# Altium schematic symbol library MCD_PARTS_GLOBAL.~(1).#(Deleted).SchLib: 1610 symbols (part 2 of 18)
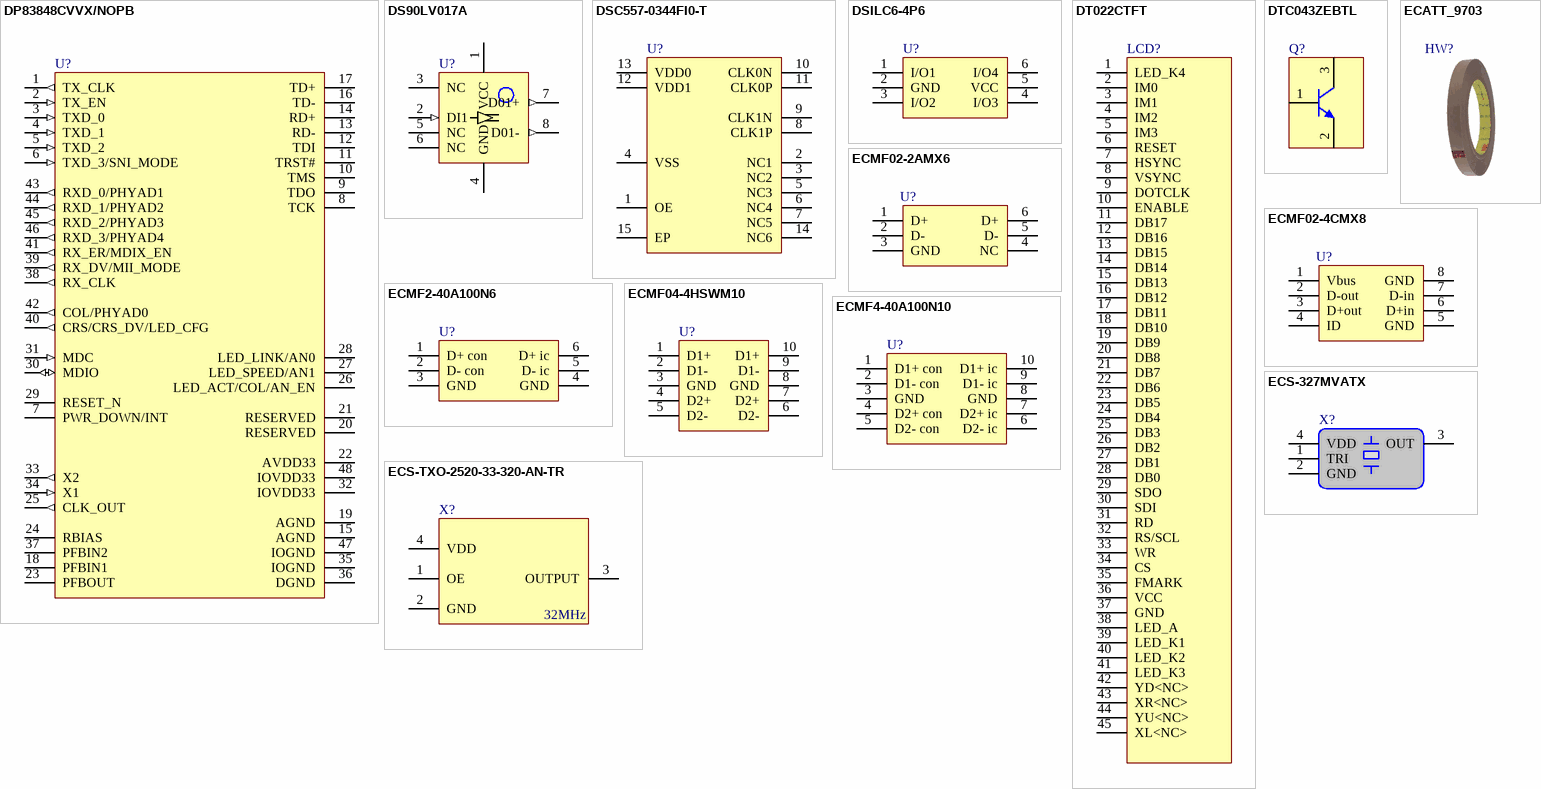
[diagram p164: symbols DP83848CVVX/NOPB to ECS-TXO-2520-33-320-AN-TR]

## DP83848CVVX/NOPB
designator U?
pins: 1 TX_CLK (out), 2 TX_EN (in), 3 TXD_0 (in), 4 TXD_1 (in), 5 TXD_2 (in), 6 TXD_3/SNI_MODE (in), 7 PWR_DOWN/INT, 8 TCK, 9 TDO, 10 TMS, 11 TRST#, 12 TDI, 13 RD-, 14 RD+, 15 AGND, 16 TD-, 17 TD+, 18 PFBIN1, 19 AGND, 20 RESERVED, 21 RESERVED, 22 AVDD33, 23 PFBOUT, 24 RBIAS, 25 CLK_OUT (out), 26 LED_ACT/COL/AN_EN, 27 LED_SPEED/AN1, 28 LED_LINK/AN0, 29 RESET_N, 30 MDIO (io), 31 MDC (in), 32 IOVDD33, 33 X2 (out), 34 X1 (in), 35 IOGND, 36 DGND, 37 PFBIN2, 38 RX_CLK (out), 39 RX_DV/MII_MODE (out), 40 CRS/CRS_DV/LED_CFG (out), 41 RX_ER/MDIX_EN (out), 42 COL/PHYAD0 (out), 43 RXD_0/PHYAD1 (out), 44 RXD_1/PHYAD2 (out), 45 RXD_2/PHYAD3 (out), 46 RXD_3/PHYAD4 (out), 47 IOGND, 48 IOVDD33

## DS90LV017A
designator U?
pins: 1 VCC (power), 2 DI1 (in), 3 NC, 4 GND, 5 NC, 6 NC, 7 D01+ (out), 8 D01- (out)

## DSC557-0344FI0-T
designator U?
pins: 1 OE, 2 NC1, 3 NC2, 4 VSS, 5 NC3, 6 NC4, 7 NC5, 8 CLK1P, 9 CLK1N, 10 CLK0N, 11 CLK0P, 12 VDD1, 13 VDD0, 14 NC6, 15 EP

## DSILC6-4P6
designator U?
pins: 1 I/O1, 2 GND, 3 I/O2, 4 I/O3, 5 VCC, 6 I/O4

## DT022CTFT
designator LCD?
pins: 1 LED_K4 , 2 IM0, 3 IM1, 4 IM2, 5 IM3, 6 RESET, 7 HSYNC, 8 VSYNC, 9 DOTCLK, 10 ENABLE, 11 DB17, 12 DB16, 13 DB15, 14 DB14, 15 DB13, 16 DB12, 17 DB11, 18 DB10, 19 DB9, 20 DB8, 21 DB7, 22 DB6, 23 DB5, 24 DB4, 25 DB3, 26 DB2, 27 DB1, 28 DB0, 29 SDO, 30 SDI, 31 RD, 32 RS/SCL, 33 WR, 34 CS, 35 FMARK, 36 VCC, 37 GND, 38 LED_A, 39 LED_K1, 40 LED_K2, 41 LED_K3, 42 YD<NC>, 43 XR<NC>, 44 YU<NC>, 45 XL<NC>

## DTC043ZEBTL
designator Q?
pins: 1 B, 2 E, 3 C

## ECATT_9703
designator HW?  (mechanical)

## ECMF02-2AMX6
designator U?
pins: 1 D+, 2 D-, 3 GND, 4 NC, 5 D-, 6 D+

## ECMF02-4CMX8
designator U?
pins: 1 Vbus, 2 D-out, 3 D+out, 4 ID, 5 GND, 6 D+in, 7 D-in, 8 GND

## ECMF2-40A100N6
designator U?
pins: 1 D+ con, 2 D- con, 3 GND, 4 GND, 5 D- ic, 6 D+ ic

## ECMF04-4HSWM10
designator U?
pins: 1 D1+, 2 D1-, 3 GND (power), 4 D2+ (oc), 5 D2- (oc), 6 D2-, 7 D2+, 8 GND (power), 9 D1-, 10 D1+

## ECMF4-40A100N10
designator U?
pins: 1 D1+ con, 2 D1- con, 3 GND, 4 D2+ con, 5 D2- con, 6 D2- ic, 7 D2+ ic, 8 GND, 9 D1- ic, 10 D1+ ic

## ECS-327MVATX
designator X?
pins: 1 TRI, 2 GND, 3 OUT, 4 VDD

## ECS-TXO-2520-33-320-AN-TR
designator X?
pins: 1 OE, 2 GND, 3 OUTPUT, 4 VDD

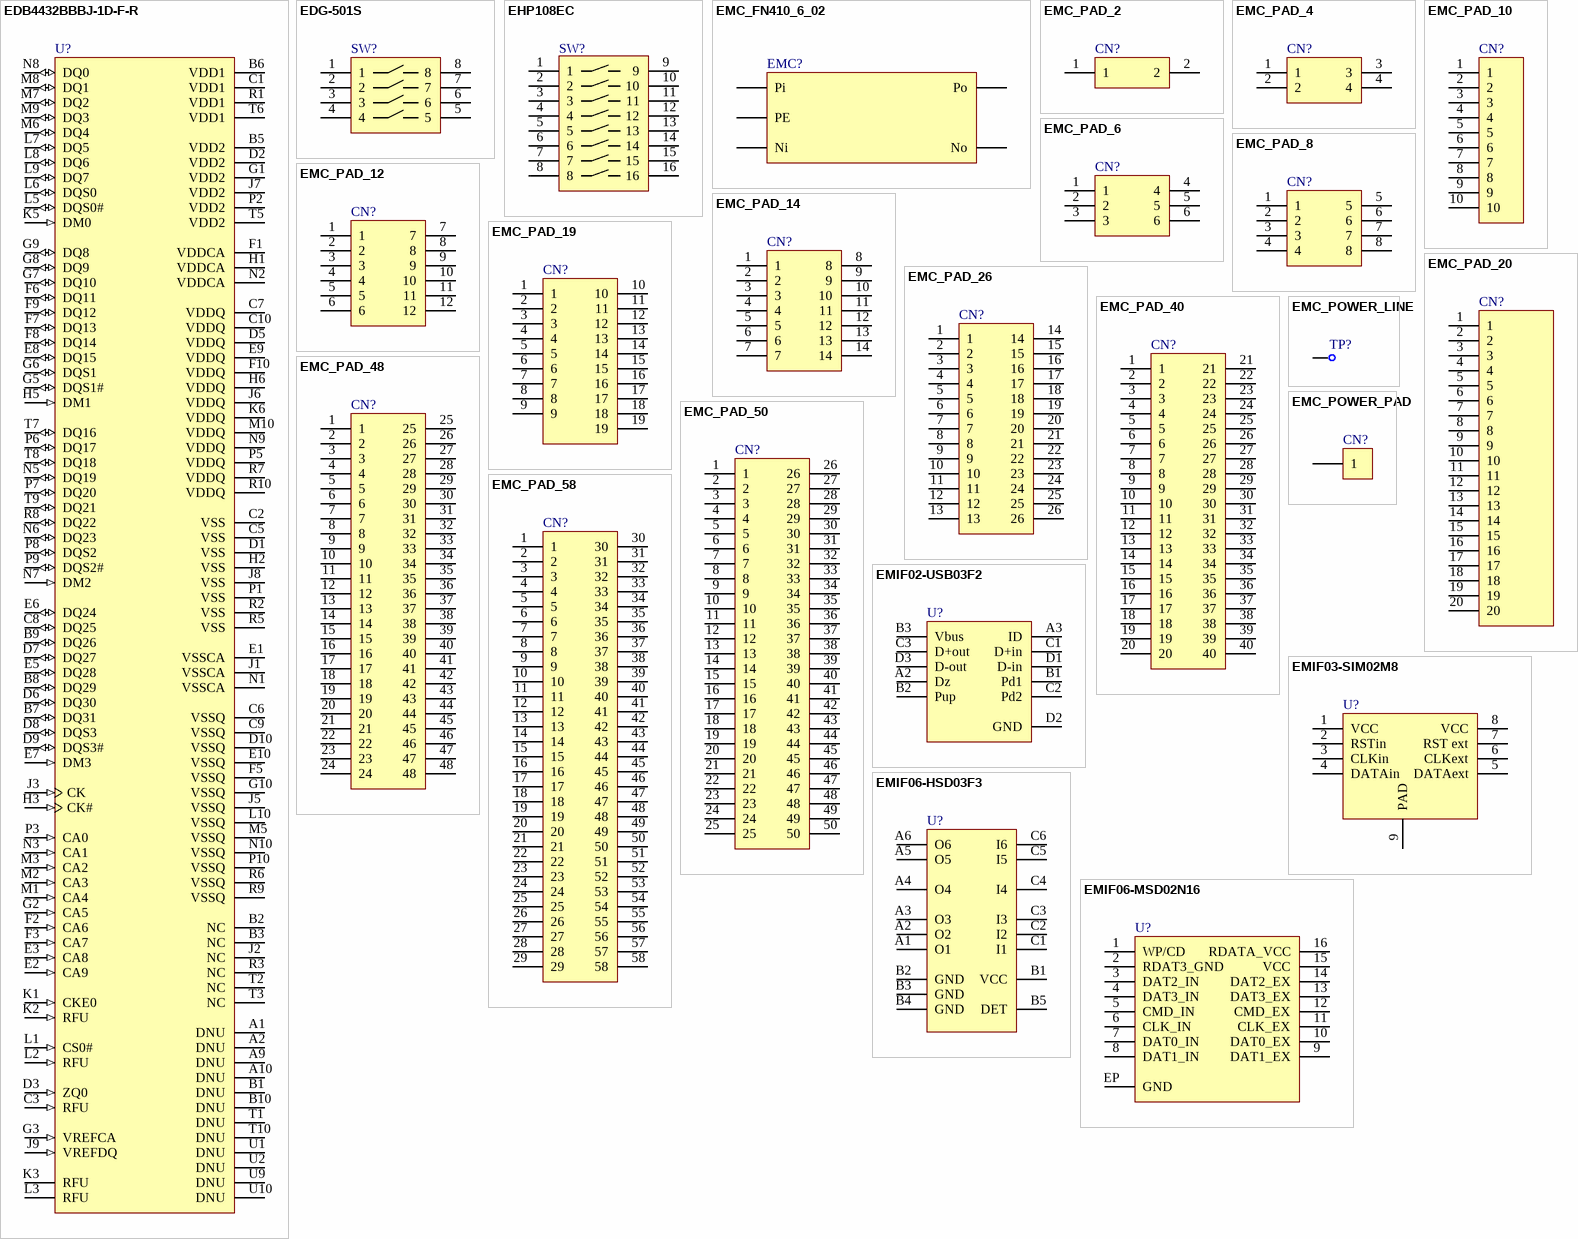
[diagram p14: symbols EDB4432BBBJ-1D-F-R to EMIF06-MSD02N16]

## EDB4432BBBJ-1D-F-R
designator U?
pins: A1 DNU "Do not use: Must be grounded or left floating.", A2 DNU "Do not use: Must be grounded or left floating.", A9 DNU "Do not use: Must be grounded or left floating.", A10 DNU "Do not use: Must be grounded or left floating.", B1 DNU "Do not use: Must be grounded or left floating.", B2 NC "No connect: Not internally connected.", B3 NC "No connect: Not internally connected.", B5 VDD2 (power) "Core power: Supply 2.", B6 VDD1 (power) "Core power: Supply 1.", B7 DQ31 (io) "Data input/output: Bidirectional data bus.", B8 DQ29 (io) "Data input/output: Bidirectional data bus.", B9 DQ26 (io) "Data input/output: Bidirectional data bus.", B10 DNU "Do not use: Must be grounded or left floating.", C1 VDD1 (power) "Core power: Supply 1.", C2 VSS (power) "Common ground.", C3 RFU (in) "External impedance (240 ohm): This signal is used to calibrate the device output impedance.", C5 VSS (power) "Common ground.", C6 VSSQ (power) "DQ ground: Isolated on the die for improved noise immunity.", C7 VDDQ (power) "DQ power supply: Isolated on the die for improved noise immunity.", C8 DQ25 (io) "Data input/output: Bidirectional data bus.", C9 VSSQ (power) "DQ ground: Isolated on the die for improved noise immunity.", C10 VDDQ (power) "DQ power supply: Isolated on the die for improved noise immunity.", D1 VSS (power) "Common ground", D2 VDD2 (power) "Core power: Supply 2.", D3 ZQ0 (in) "External impedance (240 ohm): This signal is used to calibrate the device output impedance.", D5 VDDQ (power) "DQ power supply: Isolated on the die for improved noise immunity.", D6 DQ30 (io) "Data input/output: Bidirectional data bus.", D7 DQ27 (io) "Data input/output: Bidirectional data bus.", D8 DQS3 (io) "Data strobe: The data strobe is bidirectional (used for read and write data) andcomplementary (DQS and DQS#). It is edge-aligned output with read data andcentered input with write data. DQS[3:0]/DQS[3:0]# is DQS for each of (See Datasheet)", D9 DQS3# (io) "Data strobe: The data strobe is bidirectional (used for read and write data) andcomplementary (DQS and DQS#). It is edge-aligned output with read data andcentered input with write data. DQS[3:0]/DQS[3:0]# is DQS for each of (See Datasheet)", D10 VSSQ (power) "DQ ground: Isolated on the die for improved noise immunity.", E1 VSSCA (power) "Command/address ground: Isolated on the die for improved noise immunity.", E2 CA9 (in) "Command/address inputs: Provide the command and address inputs accordingto the command truth table.", E3 CA8 (in) "Command/address inputs: Provide the command and address inputs accordingto the command truth table.", E5 DQ28 (io) "Data input/output: Bidirectional data bus.", E6 DQ24 (io) "Data input/output: Bidirectional data bus.", E7 DM3 (in) "Input data mask: DM is an input mask signal for write data. Although DM ballsare input-only, the DM loading is designed to match that of DQ and DQS balls.DM[3:0] is DM for each of the four data bytes, respectively.", E8 DQ15 (io) "Data input/output: Bidirectional data bus.", E9 VDDQ (power) "DQ power supply: Isolated on the die for improved noise immunity.", E10 VSSQ (power) "DQ ground: Isolated on the die for improved noise immunity.", F1 VDDCA (power) "Command/address power supply: Command/address power supply.", F2 CA6 (in) "Command/address inputs: Provide the command and address inputs accordingto the command truth table.", F3 CA7 (in) "Command/address inputs: Provide the command and address inputs accordingto the command truth table.", F5 VSSQ (power) "DQ ground: Isolated on the die for improved noise immunity.", F6 DQ11 (io) "Data input/output: Bidirectional data bus.", F7 DQ13 (io) "Data input/output: Bidirectional data bus.", F8 DQ14 (io) "Data input/output: Bidirectional data bus.", F9 DQ12 (io) "Data input/output: Bidirectional data bus.", F10 VDDQ (power) "DQ power supply: Isolated on the die for improved noise immunity.", G1 VDD2 (power) "Core power: Supply 2.", G2 CA5 (in) "Command/address inputs: Provide the command and address inputs accordingto the command truth table.", G3 VREFCA (in) "Reference voltage: VREFCA is reference for command/address input buffers,VREFDQ is reference for DQ input buffers.", G5 DQS1# (io) "Data strobe: The data strobe is bidirectional (used for read and write data) andcomplementary (DQS and DQS#). It is edge-aligned output with read data andcentered input with write data. DQS[3:0]/DQS[3:0]# is DQS for each of (See Datasheet)", G6 DQS1 (io) "Data strobe: The data strobe is bidirectional (used for read and write data) andcomplementary (DQS and DQS#). It is edge-aligned output with read data andcentered input with write data. DQS[3:0]/DQS[3:0]# is DQS for each of (See Datasheet)", G7 DQ10 (io) "Data input/output: Bidirectional data bus.", G8 DQ9 (io) "Data input/output: Bidirectional data bus.", G9 DQ8 (io) "Data input/output: Bidirectional data bus.", G10 VSSQ (power) "DQ ground: Isolated on the die for improved noise immunity.", H1 VDDCA (power) "Command/address power supply: Command/address power supply.", H2 VSS (power) "Common ground", H3 CK# (in) "Clock: CK and CK# are differential clock inputs. All CA inputs are sampled onboth rising and falling edges of CK. CS and CKE inputs are sampled at the risingedge of CK. AC timings are referenced to clock.", H5 DM1 (in) "Input data mask: DM is an input mask signal for write data. Although DM ballsare input-only, the DM loading is designed to match that of DQ and DQS balls.DM[3:0] is DM for each of the four data bytes, respectively.", H6 VDDQ (power) "DQ power supply: Isolated on the die for improved noise immunity.", J1 VSSCA (power) "Command/address ground: Isolated on the die for improved noise immunity.", J2 NC "No connect: Not internally connected.", J3 CK (in) "Clock: CK and CK# are differential clock inputs. All CA inputs are sampled onboth rising and falling edges of CK. CS and CKE inputs are sampled at the risingedge of CK. AC timings are referenced to clock.", J5 VSSQ (power) "DQ ground: Isolated on the die for improved noise immunity.", J6 VDDQ (power) "DQ power supply: Isolated on the die for improved noise immunity.", J7 VDD2 (power) "Core power: Supply 2.", J8 VSS (power) "Common ground", J9 VREFDQ (in) "Reference voltage: VREFCA is reference for command/address input buffers,VREFDQ is reference for DQ input buffers.", K1 CKE0 (in) "Clock enable: CKE HIGH activates and CKE LOW deactivates the internal clocksignals, input buffers, and output drivers. Power-saving modes are entered andexited via CKE transitions. CKE is considered part of the command code. (See Datasheet)", K2 RFU (in) "Clock enable: CKE HIGH activates and CKE LOW deactivates the internal clocksignals, input buffers, and output drivers. Power-saving modes are entered andexited via CKE transitions. CKE is considered part of the command code. (See Datasheet)", K3 RFU, K5 DM0 (in) "Input data mask: DM is an input mask signal for write data. Although DM ballsare input-only, the DM loading is designed to match that of DQ and DQS balls.DM[3:0] is DM for each of the four data bytes, respectively.", K6 VDDQ (power) "DQ power supply: Isolated on the die for improved noise immunity.", L1 CS0# (in) "Chip select: CS# is considered part of the command code and is sampled at therising edge of CK.", L2 RFU (in) "Chip select: CS# is considered part of the command code and is sampled at therising edge of CK.", L3 RFU, L5 DQS0# (io) "Data strobe: The data strobe is bidirectional (used for read and write data) andcomplementary (DQS and DQS#). It is edge-aligned output with read data andcentered input with write data. DQS[3:0]/DQS[3:0]# is DQS for each of (See Datasheet)", L6 DQS0 (io) "Data strobe: The data strobe is bidirectional (used for read and write data) andcomplementary (DQS and DQS#). It is edge-aligned output with read data andcentered input with write data. DQS[3:0]/DQS[3:0]# is DQS for each of (See Datasheet)", L7 DQ5 (io) "Data input/output: Bidirectional data bus.", L8 DQ6 (io) "Data input/output: Bidirectional data bus.", L9 DQ7 (io) "Data input/output: Bidirectional data bus.", L10 VSSQ (power) "DQ ground: Isolated on the die for improved noise immunity.", M1 CA4 (in) "Command/address inputs: Provide the command and address inputs accordingto the command truth table.", M2 CA3 (in) "Command/address inputs: Provide the command and address inputs accordingto the command truth table.", M3 CA2 (in) "Command/address inputs: Provide the command and address inputs accordingto the command truth table.", M5 VSSQ (power) "DQ ground: Isolated on the die for improved noise immunity.", M6 DQ4 (io) "Data input/output: Bidirectional data bus.", M7 DQ2 (io) "Data input/output: Bidirectional data bus.", M8 DQ1 (io) "Data input/output: Bidirectional data bus.", M9 DQ3 (io) "Data input/output: Bidirectional data bus.", M10 VDDQ (power) "DQ power supply: Isolated on the die for improved noise immunity.", N1 VSSCA (power) "Command/address ground: Isolated on the die for improved noise immunity.", N2 VDDCA (power) "Command/address power supply: Command/address power supply.", N3 CA1 (in) "Command/address inputs: Provide the command and address inputs accordingto the command truth table.", N5 DQ19 (io) "Data input/output: Bidirectional data bus.", N6 DQ23 (io) "Data input/output: Bidirectional data bus.", N7 DM2 (in) "Input data mask: DM is an input mask signal for write data. Although DM ballsare input-only, the DM loading is designed to match that of DQ and DQS balls.DM[3:0] is DM for each of the four data bytes, respectively.", N8 DQ0 (io) "Data input/output: Bidirectional data bus.", N9 VDDQ (power) "DQ power supply: Isolated on the die for improved noise immunity.", N10 VSSQ (power) "DQ ground: Isolated on the die for improved noise immunity.", P1 VSS (power) "Common ground", P2 VDD2 (power) "Core power: Supply 2.", P3 CA0 (in) "Command/address inputs: Provide the command and address inputs accordingto the command truth table.", P5 VDDQ (power) "DQ power supply: Isolated on the die for improved noise immunity.", P6 DQ17 (io) "Data input/output: Bidirectional data bus.", P7 DQ20 (io) "Data input/output: Bidirectional data bus.", P8 DQS2 (io) "Data strobe: The data strobe is bidirectional (used for read and write data) andcomplementary (DQS and DQS#). It is edge-aligned output with read data andcentered input with write data. DQS[3:0]/DQS[3:0]# is DQS for each of (See Datasheet)", P9 DQS2# (io) "Data strobe: The data strobe is bidirectional (used for read and write data) andcomplementary (DQS and DQS#). It is edge-aligned output with read data andcentered input with write data. DQS[3:0]/DQS[3:0]# is DQS for each of (See Datasheet)", P10 VSSQ (power) "DQ ground: Isolated on the die for improved noise immunity.", R1 VDD1 (power) "Core power: Supply 1.", R2 VSS (power) "Common ground", R3 NC "No connect: Not internally connected.", R5 VSS (power) "Common ground", R6 VSSQ (power) "DQ ground: Isolated on the die for improved noise immunity.", R7 VDDQ (power) "DQ power supply: Isolated on the die for improved noise immunity.", R8 DQ22 (io) "Data input/output: Bidirectional data bus.", R9 VSSQ (power) "DQ ground: Isolated on the die for improved noise immunity.", R10 VDDQ (power) "DQ power supply: Isolated on the die for improved noise immunity.", T1 DNU "Do not use: Must be grounded or left floating.", T2 NC "No connect: Not internally connected.", T3 NC "No connect: Not internally connected.", T5 VDD2 (power) "Core power: Supply 2.", T6 VDD1 (power) "Core power: Supply 1.", T7 DQ16 (io) "Data input/output: Bidirectional data bus.", T8 DQ18 (io) "Data input/output: Bidirectional data bus.", T9 DQ21 (io) "Data input/output: Bidirectional data bus.", T10 DNU "Do not use: Must be grounded or left floating.", U1 DNU "Do not use: Must be grounded or left floating.", U2 DNU "Do not use: Must be grounded or left floating.", U9 DNU "Do not use: Must be grounded or left floating.", U10 DNU "Do not use: Must be grounded or left floating."

## EDG-501S
designator SW?
pins: 1, 2, 3, 4, 5, 6, 7, 8

## EHP108EC
designator SW?
pins: 1, 2, 3, 4, 5, 6, 7, 8, 9, 10, 11, 12, 13, 14, 15, 16

## EMC_FN410_6_02
designator EMC?
pins: Ni, No, PE, Pi, Po

## EMC_PAD_2
designator CN?  (no BOM)
pins: 1, 2

## EMC_PAD_4
designator CN?  (no BOM)
pins: 1, 2, 3, 4

## EMC_PAD_6
designator CN?  (no BOM)
pins: 1, 2, 3, 4, 5, 6

## EMC_PAD_8
designator CN?  (no BOM)
pins: 1, 2, 3, 4, 5, 6, 7, 8

## EMC_PAD_10
designator CN?  (no BOM)
pins: 1, 2, 3, 4, 5, 6, 7, 8, 9, 10

## EMC_PAD_12
designator CN?  (no BOM)
pins: 1, 2, 3, 4, 5, 6, 7, 8, 9, 10, 11, 12

## EMC_PAD_14
designator CN?  (no BOM)
pins: 1, 2, 3, 4, 5, 6, 7, 8, 9, 10, 11, 12, 13, 14

## EMC_PAD_19
designator CN?  (no BOM)
pins: 1, 2, 3, 4, 5, 6, 7, 8, 9, 10, 11, 12, 13, 14, 15, 16, 17, 18, 19

## EMC_PAD_20
designator CN?  (no BOM)
pins: 1, 2, 3, 4, 5, 6, 7, 8, 9, 10, 11, 12, 13, 14, 15, 16, 17, 18, 19, 20

## EMC_PAD_26
designator CN?  (no BOM)
pins: 1, 2, 3, 4, 5, 6, 7, 8, 9, 10, 11, 12, 13, 14, 15, 16, 17, 18, 19, 20, 21, 22, 23, 24, 25, 26

## EMC_PAD_40
designator CN?  (no BOM)
pins: 1, 2, 3, 4, 5, 6, 7, 8, 9, 10, 11, 12, 13, 14, 15, 16, 17, 18, 19, 20, 21, 22, 23, 24, 25, 26, 27, 28, 29, 30, 31, 32, 33, 34, 35, 36, 37, 38, 39, 40

## EMC_PAD_48
designator CN?  (no BOM)
pins: 1, 2, 3, 4, 5, 6, 7, 8, 9, 10, 11, 12, 13, 14, 15, 16, 17, 18, 19, 20, 21, 22, 23, 24, 25, 26, 27, 28, 29, 30, 31, 32, 33, 34, 35, 36, 37, 38, 39, 40, 41, 42, 43, 44, 45, 46, 47, 48

## EMC_PAD_50
designator CN?  (no BOM)
pins: 1, 2, 3, 4, 5, 6, 7, 8, 9, 10, 11, 12, 13, 14, 15, 16, 17, 18, 19, 20, 21, 22, 23, 24, 25, 26, 27, 28, 29, 30, 31, 32, 33, 34, 35, 36, 37, 38, 39, 40, 41, 42, 43, 44, 45, 46, 47, 48, 49, 50

## EMC_PAD_58
designator CN?  (no BOM)
pins: 1, 2, 3, 4, 5, 6, 7, 8, 9, 10, 11, 12, 13, 14, 15, 16, 17, 18, 19, 20, 21, 22, 23, 24, 25, 26, 27, 28, 29, 30, 31, 32, 33, 34, 35, 36, 37, 38, 39, 40, 41, 42, 43, 44, 45, 46, 47, 48, 49, 50, 51, 52, 53, 54, 55, 56, 57, 58

## EMC_POWER_LINE
designator TP?  (no BOM)
pins: 1

## EMC_POWER_PAD
designator CN?  (no BOM)
pins: 1

## EMIF02-USB03F2
designator U?
pins: A2 Dz, A3 ID, B1 Pd1, B2 Pup, B3 Vbus, C1 D+in, C2 Pd2, C3 D+out, D1 D-in, D2 GND, D3 D-out

## EMIF03-SIM02M8
designator U?
pins: 1 VCC, 2 RSTin, 3 CLKin, 4 DATAin, 5 DATAext, 6 CLKext, 7 RST ext, 8 VCC, 9 PAD

## EMIF06-HSD03F3
designator U?
pins: A1 O1, A2 O2, A3 O3, A4 O4, A5 O5, A6 O6, B1 VCC, B2 GND, B3 GND, B4 GND, B5 DET, C1 I1, C2 I2, C3 I3, C4 I4, C5 I5, C6 I6

## EMIF06-MSD02N16
designator U?
pins: 1 WP/CD, 2 RDAT3_GND, 3 DAT2_IN, 4 DAT3_IN, 5 CMD_IN, 6 CLK_IN, 7 DAT0_IN, 8 DAT1_IN, 9 DAT1_EX, 10 DAT0_EX, 11 CLK_EX, 12 CMD_EX, 13 DAT3_EX, 14 DAT2_EX, 15 VCC, 16 RDATA_VCC, EP GND
1 alternate drawing of the same symbol

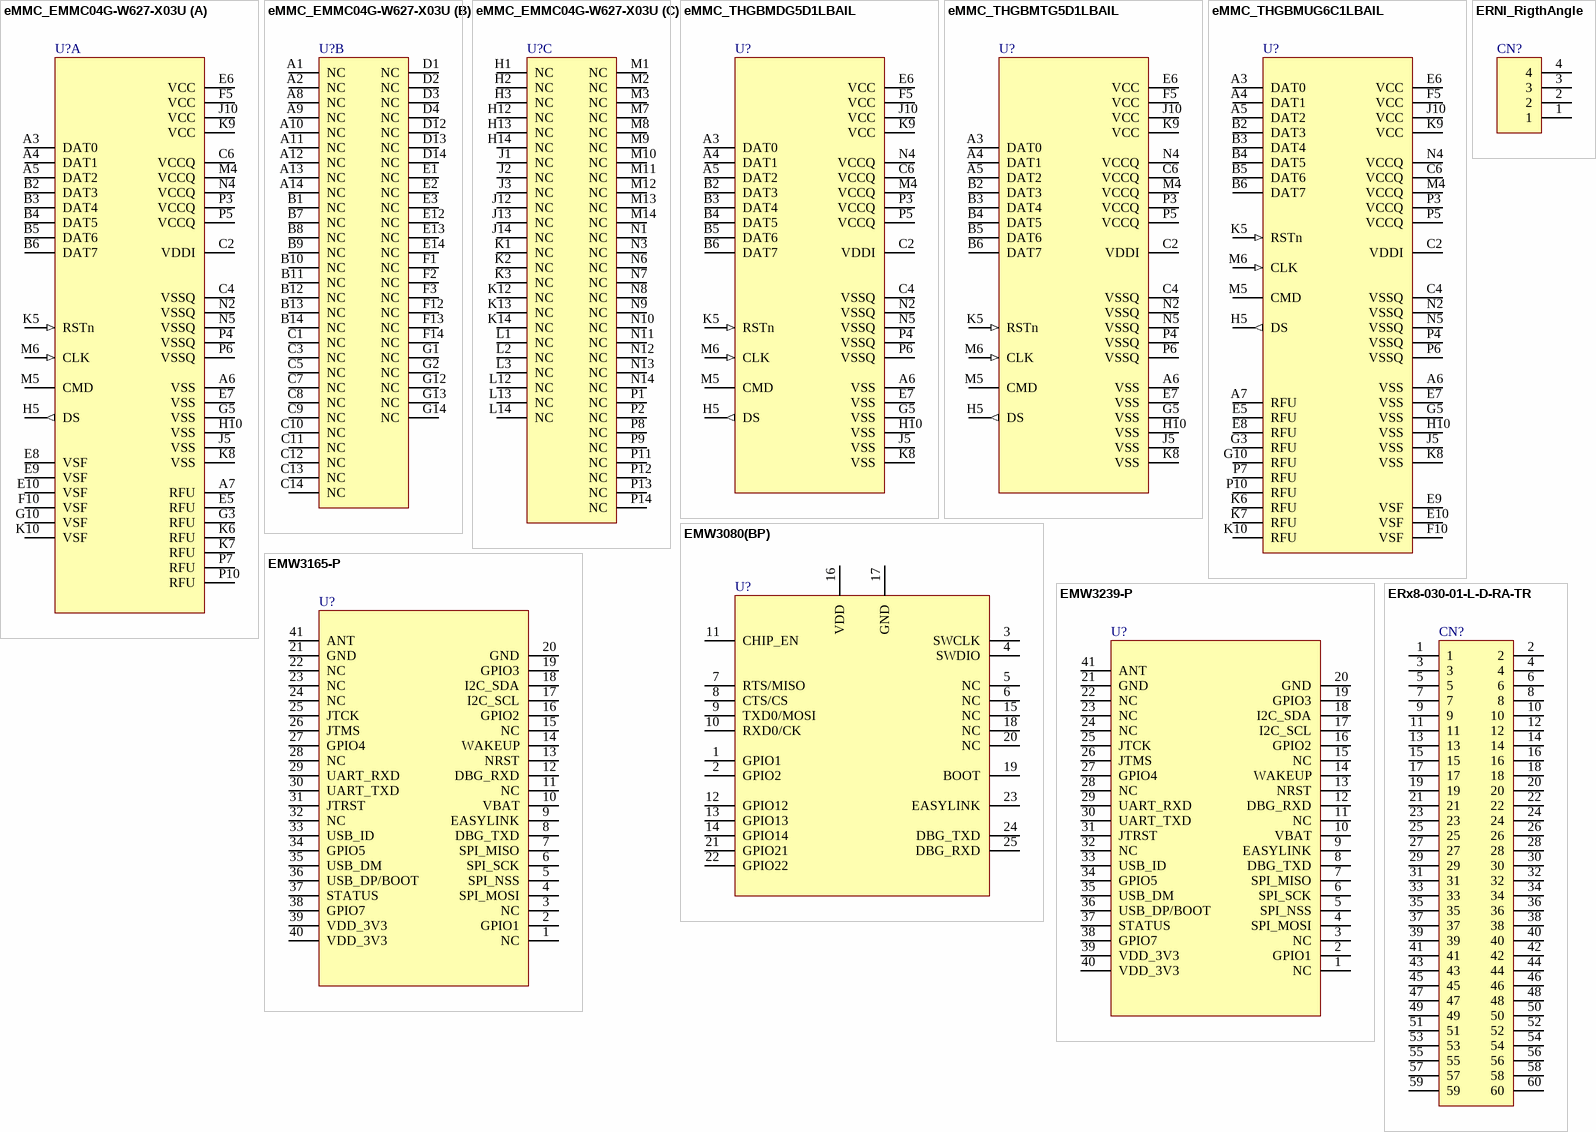
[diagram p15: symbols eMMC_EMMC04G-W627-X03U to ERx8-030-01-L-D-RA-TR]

## eMMC_EMMC04G-W627-X03U
designator U?
part A pins: A3 DAT0, A4 DAT1, A5 DAT2, A6 VSS, A7 RFU, B2 DAT3, B3 DAT4, B4 DAT5, B5 DAT6, B6 DAT7, C2 VDDI, C4 VSSQ, C6 VCCQ, E5 RFU, E6 VCC, E7 VSS, E8 VSF, E9 VSF, E10 VSF, F5 VCC, F10 VSF, G3 RFU, G5 VSS, G10 VSF, H5 DS (out), H10 VSS, J5 VSS, J10 VCC, K5 RSTn (in), K6 RFU, K7 RFU, K8 VSS, K9 VCC, K10 VSF, M4 VCCQ, M5 CMD, M6 CLK (in), N2 VSSQ, N4 VCCQ, N5 VSSQ, P3 VCCQ, P4 VSSQ, P5 VCCQ, P6 VSSQ, P7 RFU, P10 RFU
part B pins: A1 NC, A2 NC, A8 NC, A9 NC, A10 NC, A11 NC, A12 NC, A13 NC, A14 NC, B1 NC, B7 NC, B8 NC, B9 NC, B10 NC, B11 NC, B12 NC, B13 NC, B14 NC, C1 NC, C3 NC, C5 NC, C7 NC, C8 NC, C9 NC, C10 NC, C11 NC, C12 NC, C13 NC, C14 NC, D1 NC, D2 NC, D3 NC, D4 NC, D12 NC, D13 NC, D14 NC, E1 NC, E2 NC, E3 NC, E12 NC, E13 NC, E14 NC, F1 NC, F2 NC, F3 NC, F12 NC, F13 NC, F14 NC, G1 NC, G2 NC, G12 NC, G13 NC, G14 NC
part C pins: H1 NC, H2 NC, H3 NC, H12 NC, H13 NC, H14 NC, J1 NC, J2 NC, J3 NC, J12 NC, J13 NC, J14 NC, K1 NC, K2 NC, K3 NC, K12 NC, K13 NC, K14 NC, L1 NC, L2 NC, L3 NC, L12 NC, L13 NC, L14 NC, M1 NC, M2 NC, M3 NC, M7 NC, M8 NC, M9 NC, M10 NC, M11 NC, M12 NC, M13 NC, M14 NC, N1 NC, N3 NC, N6 NC, N7 NC, N8 NC, N9 NC, N10 NC, N11 NC, N12 NC, N13 NC, N14 NC, P1 NC, P2 NC, P8 NC, P9 NC, P11 NC, P12 NC, P13 NC, P14 NC

## eMMC_THGBMDG5D1LBAIL
designator U?
pins: A3 DAT0, A4 DAT1, A5 DAT2, A6 VSS, B2 DAT3, B3 DAT4, B4 DAT5, B5 DAT6, B6 DAT7, C2 VDDI, C4 VSSQ, C6 VCCQ, E6 VCC, E7 VSS, F5 VCC, G5 VSS, H5 DS (out), H10 VSS, J5 VSS, J10 VCC, K5 RSTn (in), K8 VSS, K9 VCC, M4 VCCQ, M5 CMD, M6 CLK (in), N2 VSSQ, N4 VCCQ, N5 VSSQ, P3 VCCQ, P4 VSSQ, P5 VCCQ, P6 VSSQ

## eMMC_THGBMTG5D1LBAIL
designator U?
pins: A3 DAT0, A4 DAT1, A5 DAT2, A6 VSS, B2 DAT3, B3 DAT4, B4 DAT5, B5 DAT6, B6 DAT7, C2 VDDI, C4 VSSQ, C6 VCCQ, E6 VCC, E7 VSS, F5 VCC, G5 VSS, H5 DS (out), H10 VSS, J5 VSS, J10 VCC, K5 RSTn (in), K8 VSS, K9 VCC, M4 VCCQ, M5 CMD, M6 CLK (in), N2 VSSQ, N4 VCCQ, N5 VSSQ, P3 VCCQ, P4 VSSQ, P5 VCCQ, P6 VSSQ

## eMMC_THGBMUG6C1LBAIL
designator U?
pins: A3 DAT0, A4 DAT1, A5 DAT2, A6 VSS, A7 RFU, B2 DAT3, B3 DAT4, B4 DAT5, B5 DAT6, B6 DAT7, C2 VDDI, C4 VSSQ, C6 VCCQ, E5 RFU, E6 VCC, E7 VSS, E8 RFU, E9 VSF, E10 VSF, F5 VCC, F10 VSF, G3 RFU, G5 VSS, G10 RFU, H5 DS (out), H10 VSS, J5 VSS, J10 VCC, K5 RSTn (in), K6 RFU, K7 RFU, K8 VSS, K9 VCC, K10 RFU, M4 VCCQ, M5 CMD, M6 CLK (in), N2 VSSQ, N4 VCCQ, N5 VSSQ, P3 VCCQ, P4 VSSQ, P5 VCCQ, P6 VSSQ, P7 RFU, P10 RFU

## EMW3080(BP)
designator U?
pins: 1 GPIO1, 2 GPIO2, 3 SWCLK, 4 SWDIO, 5 NC, 6 NC, 7 RTS/MISO, 8 CTS/CS, 9 TXD0/MOSI, 10 RXD0/CK, 11 CHIP_EN, 12 GPIO12, 13 GPIO13, 14 GPIO14, 15 NC, 16 VDD, 17 GND, 18 NC, 19 BOOT, 20 NC, 21 GPIO21, 22 GPIO22, 23 EASYLINK, 24 DBG_TXD, 25 DBG_RXD

## EMW3165-P
designator U?
pins: 1 NC, 2 GPIO1, 3 NC, 4 SPI_MOSI, 5 SPI_NSS, 6 SPI_SCK, 7 SPI_MISO, 8 DBG_TXD, 9 EASYLINK, 10 VBAT, 11 NC, 12 DBG_RXD, 13 NRST, 14 WAKEUP, 15 NC, 16 GPIO2, 17 I2C_SCL, 18 I2C_SDA, 19 GPIO3, 20 GND, 21 GND, 22 NC, 23 NC, 24 NC, 25 JTCK, 26 JTMS, 27 GPIO4, 28 NC, 29 UART_RXD, 30 UART_TXD, 31 JTRST, 32 NC, 33 USB_ID, 34 GPIO5, 35 USB_DM, 36 USB_DP/BOOT, 37 STATUS, 38 GPIO7, 39 VDD_3V3, 40 VDD_3V3, 41 ANT

## EMW3239-P
designator U?
pins: 1 NC, 2 GPIO1, 3 NC, 4 SPI_MOSI, 5 SPI_NSS, 6 SPI_SCK, 7 SPI_MISO, 8 DBG_TXD, 9 EASYLINK, 10 VBAT, 11 NC, 12 DBG_RXD, 13 NRST, 14 WAKEUP, 15 NC, 16 GPIO2, 17 I2C_SCL, 18 I2C_SDA, 19 GPIO3, 20 GND, 21 GND, 22 NC, 23 NC, 24 NC, 25 JTCK, 26 JTMS, 27 GPIO4, 28 NC, 29 UART_RXD, 30 UART_TXD, 31 JTRST, 32 NC, 33 USB_ID, 34 GPIO5, 35 USB_DM, 36 USB_DP/BOOT, 37 STATUS, 38 GPIO7, 39 VDD_3V3, 40 VDD_3V3, 41 ANT

## ERNI_RigthAngle
designator CN?
pins: 1, 2, 3, 4

## ERx8-030-01-L-D-RA-TR
designator CN?
pins: 1, 2, 3, 4, 5, 6, 7, 8, 9, 10, 11, 12, 13, 14, 15, 16, 17, 18, 19, 20, 21, 22, 23, 24, 25, 26, 27, 28, 29, 30, 31, 32, 33, 34, 35, 36, 37, 38, 39, 40, 41, 42, 43, 44, 45, 46, 47, 48, 49, 50, 51, 52, 53, 54, 55, 56, 57, 58, 59, 60

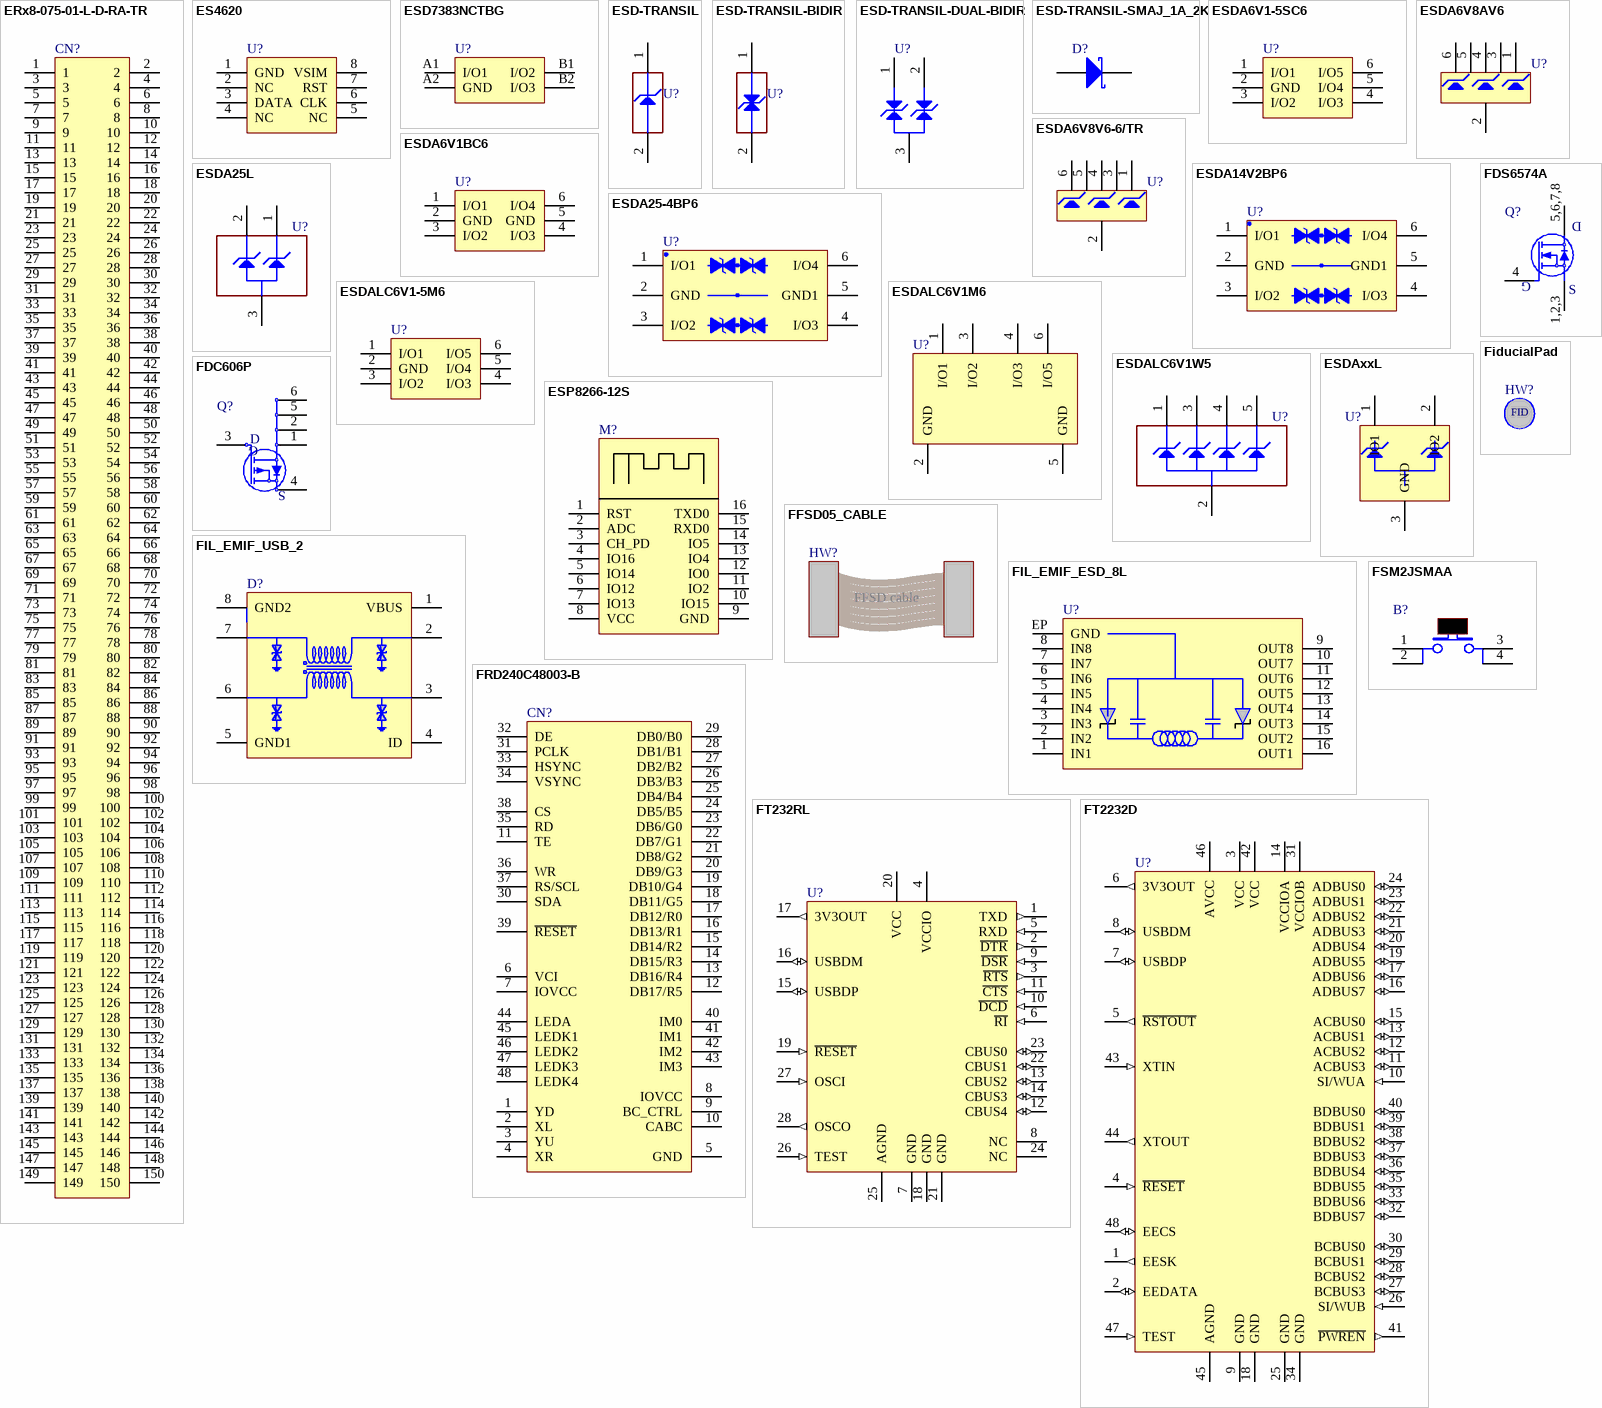
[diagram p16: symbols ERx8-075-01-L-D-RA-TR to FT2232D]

## ERx8-075-01-L-D-RA-TR
designator CN?
pins: 1, 2, 3, 4, 5, 6, 7, 8, 9, 10, 11, 12, 13, 14, 15, 16, 17, 18, 19, 20, 21, 22, 23, 24, 25, 26, 27, 28, 29, 30, 31, 32, 33, 34, 35, 36, 37, 38, 39, 40, 41, 42, 43, 44, 45, 46, 47, 48, 49, 50, 51, 52, 53, 54, 55, 56, 57, 58, 59, 60, 61, 62, 63, 64, 65, 66, 67, 68, 69, 70, 71, 72, 73, 74, 75, 76, 77, 78, 79, 80, 81, 82, 83, 84, 85, 86, 87, 88, 89, 90, 91, 92, 93, 94, 95, 96, 97, 98, 99, 100, 101, 102, 103, 104, 105, 106, 107, 108, 109, 110, 111, 112, 113, 114, 115, 116, 117, 118, 119, 120, 121, 122, 123, 124, 125, 126, 127, 128, 129, 130, 131, 132, 133, 134, 135, 136, 137, 138, 139, 140, 141, 142, 143, 144, 145, 146, 147, 148, 149, 150

## ES4620
designator U?
pins: 1 GND, 2 NC, 3 DATA, 4 NC, 5 NC, 6 CLK, 7 RST, 8 VSIM

## ESD7383NCTBG
designator U?
pins: A1 I/O1, A2 GND, B1 I/O2, B2 I/O3

## ESD-TRANSIL
designator U?
pins: 1 IO1, 2 GND

## ESD-TRANSIL-BIDIR
designator U?
pins: 1 IO1, 2 GND

## ESD-TRANSIL-DUAL-BIDIR
designator U?
pins: 1, 2, 3

## ESD-TRANSIL-SMAJ_1A_2K
designator D?
pins: 1 A, 2 K

## ESDA6V1-5SC6
designator U?
pins: 1 I/O1, 2 GND, 3 I/O2, 4 I/O3, 5 I/O4, 6 I/O5

## ESDA6V1BC6
designator U?
pins: 1 I/O1, 2 GND, 3 I/O2, 4 I/O3, 5 GND, 6 I/O4

## ESDA6V8AV6
designator U?
pins: 1, 2, 3, 4, 5, 6

## ESDA6V8V6-6/TR
designator U?
pins: 1, 2, 3, 4, 5, 6

## ESDA14V2BP6
designator U?
pins: 1 I/O1, 2 GND, 3 I/O2, 4 I/O3, 5 GND1, 6 I/O4

## ESDA25-4BP6
designator U?
pins: 1 I/O1, 2 GND, 3 I/O2, 4 I/O3, 5 GND1, 6 I/O4

## ESDA25L
designator U?
pins: 1 IO1, 2 IO2, 3 GND

## ESDALC6V1-5M6
designator U?
pins: 1 I/O1, 2 GND, 3 I/O2, 4 I/O3, 5 I/O4, 6 I/O5

## ESDALC6V1M6
designator U?
pins: 1 I/O1, 2 GND, 3 I/O2, 4 I/O3, 5 GND, 6 I/O5

## ESDALC6V1W5
designator U?
pins: 1 IO1, 2 GND, 3 IO2, 4 IO3, 5 IO4

## ESDAxxL
designator U?
pins: 1 IO1, 2 IO2, 3 GND

## ESP8266-12S
designator M?
pins: 1 RST, 2 ADC, 3 CH_PD, 4 IO16, 5 IO14, 6 IO12, 7 IO13, 8 VCC, 9 GND, 10 IO15, 11 IO2, 12 IO0, 13 IO4, 14 IO5, 15 RXD0, 16 TXD0

## FDC606P
designator Q?
pins: 1 S, 2 S, 3 G, 4 S, 5 D, 6 D

## FDS6574A
designator Q?
pins: 1,2,3 S, 4 G, 5,6,7,8 D

## FFSD05_CABLE
designator HW?

## FiducialPad
designator HW?  (no BOM)

## FIL_EMIF_ESD_8L
designator U?
pins: 1 IN1, 2 IN2, 3 IN3, 4 IN4, 5 IN5, 6 IN6, 7 IN7, 8 IN8, 9 OUT8, 10 OUT7, 11 OUT6, 12 OUT5, 13 OUT4, 14 OUT3, 15 OUT2, 16 OUT1, EP GND

## FIL_EMIF_USB_2
designator D?
pins: 1 VBUS, 2 D-1, 3 D+1, 4 ID, 5 GND1, 6 D+2, 7 D-2, 8 GND2

## FRD240C48003-B
designator CN?
pins: 1 YD, 2 XL, 3 YU, 4 XR, 5 GND, 6 VCI, 7 IOVCC, 8 IOVCC, 9 BC_CTRL, 10 CABC, 11 TE, 12 DB17/R5, 13 DB16/R4, 14 DB15/R3, 15 DB14/R2, 16 DB13/R1, 17 DB12/R0, 18 DB11/G5, 19 DB10/G4, 20 DB9/G3, 21 DB8/G2, 22 DB7/G1, 23 DB6/G0, 24 DB5/B5, 25 DB4/B4, 26 DB3/B3, 27 DB2/B2, 28 DB1/B1, 29 DB0/B0, 30 SDA, 31 PCLK, 32 DE, 33 HSYNC, 34 VSYNC, 35 RD, 36 WR, 37 RS/SCL, 38 CS, 39 ~{RESET}, 40 IM0, 41 IM1, 42 IM2, 43 IM3, 44 LEDA, 45 LEDK1, 46 LEDK2, 47 LEDK3, 48 LEDK4

## FSM2JSMAA
designator B?
pins: 1, 2, 3, 4

## FT232RL
designator U?
pins: 1 TXD (out), 2 ~{DTR} (out), 3 ~{RTS} (out), 4 VCCIO (power), 5 RXD (in), 6 ~{RI} (in), 7 GND (power), 8 NC, 9 ~{DSR} (in), 10 ~{DCD} (in), 11 ~{CTS} (in), 12 CBUS4 (io), 13 CBUS2 (io), 14 CBUS3 (io), 15 USBDP (io), 16 USBDM (io), 17 3V3OUT (out), 18 GND (power), 19 ~{RESET} (in), 20 VCC (power), 21 GND (power), 22 CBUS1 (io), 23 CBUS0 (io), 24 NC, 25 AGND (power), 26 TEST (in), 27 OSCI (in), 28 OSCO (out)

## FT2232D
designator U?
pins: 1 EESK (out), 2 EEDATA (io), 3 VCC (power), 4 ~{RESET} (in), 5 ~{RSTOUT} (out), 6 3V3OUT (out), 7 USBDP (io), 8 USBDM (io), 9 GND (power), 10 SI/WUA (in), 11 ACBUS3 (io), 12 ACBUS2 (io), 13 ACBUS1 (io), 14 VCCIOA (power), 15 ACBUS0 (io), 16 ADBUS7 (io), 17 ADBUS6 (io), 18 GND (power), 19 ADBUS5 (io), 20 ADBUS4 (io), 21 ADBUS3 (io), 22 ADBUS2 (io), 23 ADBUS1 (io), 24 ADBUS0 (io), 25 GND (power), 26 SI/WUB (in), 27 BCBUS3 (io), 28 BCBUS2 (io), 29 BCBUS1 (io), 30 BCBUS0 (io), 31 VCCIOB (power), 32 BDBUS7 (io), 33 BDBUS6 (io), 34 GND (power), 35 BDBUS5 (io), 36 BDBUS4 (io), 37 BDBUS3 (io), 38 BDBUS2 (io), 39 BDBUS1 (io), 40 BDBUS0 (io), 41 ~{PWREN} (out), 42 VCC (power), 43 XTIN (in), 44 XTOUT (out), 45 AGND (power), 46 AVCC (power), 47 TEST (in), 48 EECS (io)

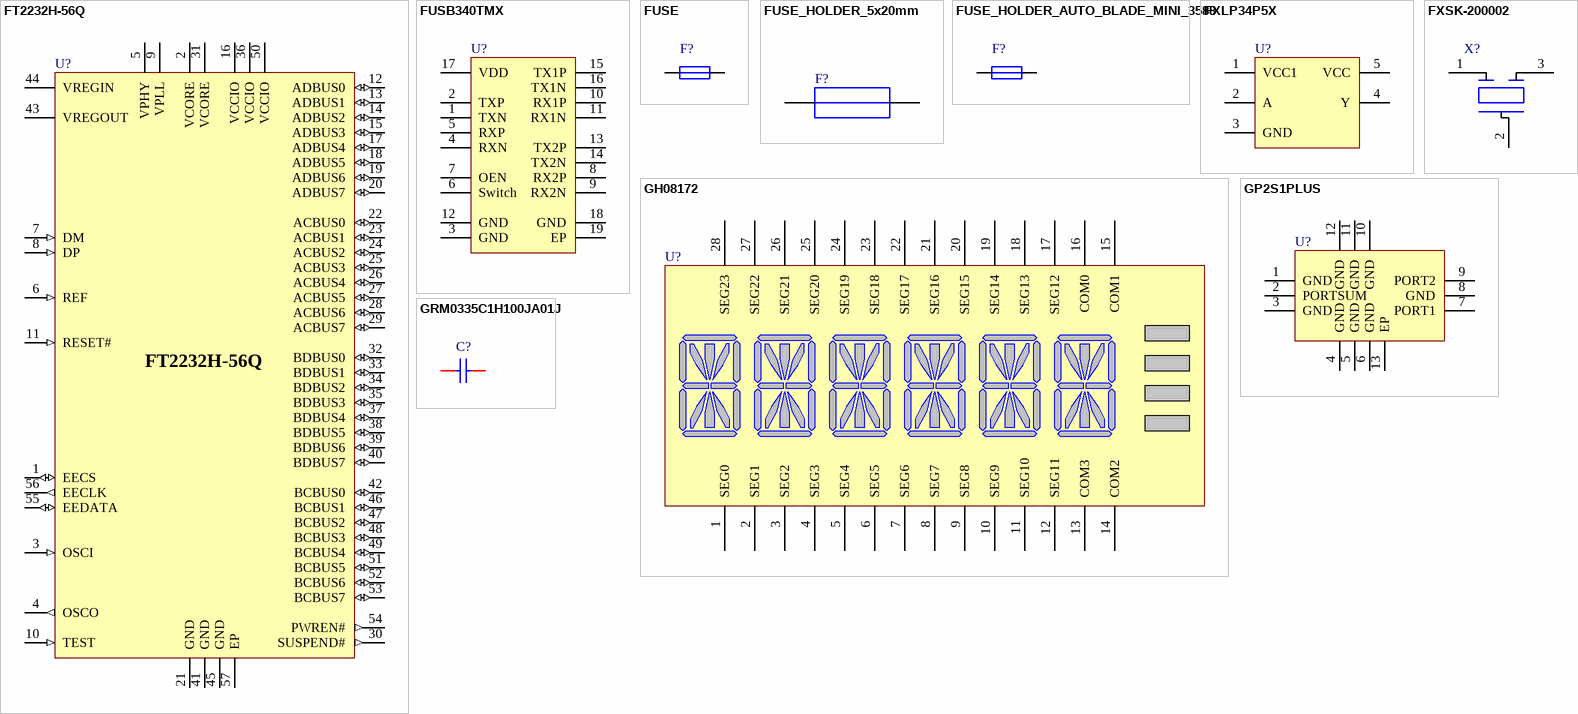
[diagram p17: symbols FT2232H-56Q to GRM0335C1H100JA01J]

## FT2232H-56Q
designator U?
pins: 1 EECS (io), 2 VCORE (power), 3 OSCI (in), 4 OSCO (out), 5 VPHY (power), 6 REF (in), 7 DM (in), 8 DP (in), 9 VPLL (power), 10 TEST (in), 11 RESET# (in), 12 ADBUS0 (io), 13 ADBUS1 (io), 14 ADBUS2 (io), 15 ADBUS3 (io), 16 VCCIO (power), 17 ADBUS4 (io), 18 ADBUS5 (io), 19 ADBUS6 (io), 20 ADBUS7 (io), 21 GND (power), 22 ACBUS0 (io), 23 ACBUS1 (io), 24 ACBUS2 (io), 25 ACBUS3 (io), 26 ACBUS4 (io), 27 ACBUS5 (io), 28 ACBUS6 (io), 29 ACBUS7 (io), 30 SUSPEND# (out), 31 VCORE (power), 32 BDBUS0 (io), 33 BDBUS1 (io), 34 BDBUS2 (io), 35 BDBUS3 (io), 36 VCCIO (power), 37 BDBUS4 (io), 38 BDBUS5 (io), 39 BDBUS6 (io), 40 BDBUS7 (io), 41 GND (power), 42 BCBUS0 (io), 43 VREGOUT (power), 44 VREGIN (power), 45 GND (power), 46 BCBUS1 (io), 47 BCBUS2 (io), 48 BCBUS3 (io), 49 BCBUS4 (io), 50 VCCIO (power), 51 BCBUS5 (io), 52 BCBUS6 (io), 53 BCBUS7 (io), 54 PWREN# (out), 55 EEDATA (io), 56 EECLK (out), 57 EP (power)

## FUSB340TMX
designator U?
pins: 1 TXN, 2 TXP, 3 GND, 4 RXN, 5 RXP, 6 Switch, 7 OEN, 8 RX2P, 9 RX2N, 10 RX1P, 11 RX1N, 12 GND, 13 TX2P, 14 TX2N, 15 TX1P, 16 TX1N, 17 VDD, 18 GND, 19 EP

## FUSE
designator F?
pins: 1, 2

## FUSE_HOLDER_5x20mm
designator F?
pins: 1, 2

## FUSE_HOLDER_AUTO_BLADE_MINI_3588
designator F?
pins: 1, 2

## FXLP34P5X
designator U?
pins: 1 VCC1, 2 A, 3 GND, 4 Y, 5 VCC

## FXSK-200002
designator X?
pins: 1 "Xin", 2, 3 "XOUT"

## GH08172
designator U?
pins: 1 SEG0, 2 SEG1, 3 SEG2, 4 SEG3, 5 SEG4, 6 SEG5, 7 SEG6, 8 SEG7, 9 SEG8, 10 SEG9, 11 SEG10, 12 SEG11, 13 COM3, 14 COM2, 15 COM1, 16 COM0, 17 SEG12, 18 SEG13, 19 SEG14, 20 SEG15, 21 SEG16, 22 SEG17, 23 SEG18, 24 SEG19, 25 SEG20, 26 SEG21, 27 SEG22, 28 SEG23

## GP2S1PLUS
designator U?
pins: 1 GND, 2 PORTSUM, 3 GND, 4 GND, 5 GND, 6 GND, 7 PORT1, 8 GND, 9 PORT2, 10 GND, 11 GND, 12 GND, 13 EP

## GRM0335C1H100JA01J
designator C?
pins: 1, 2

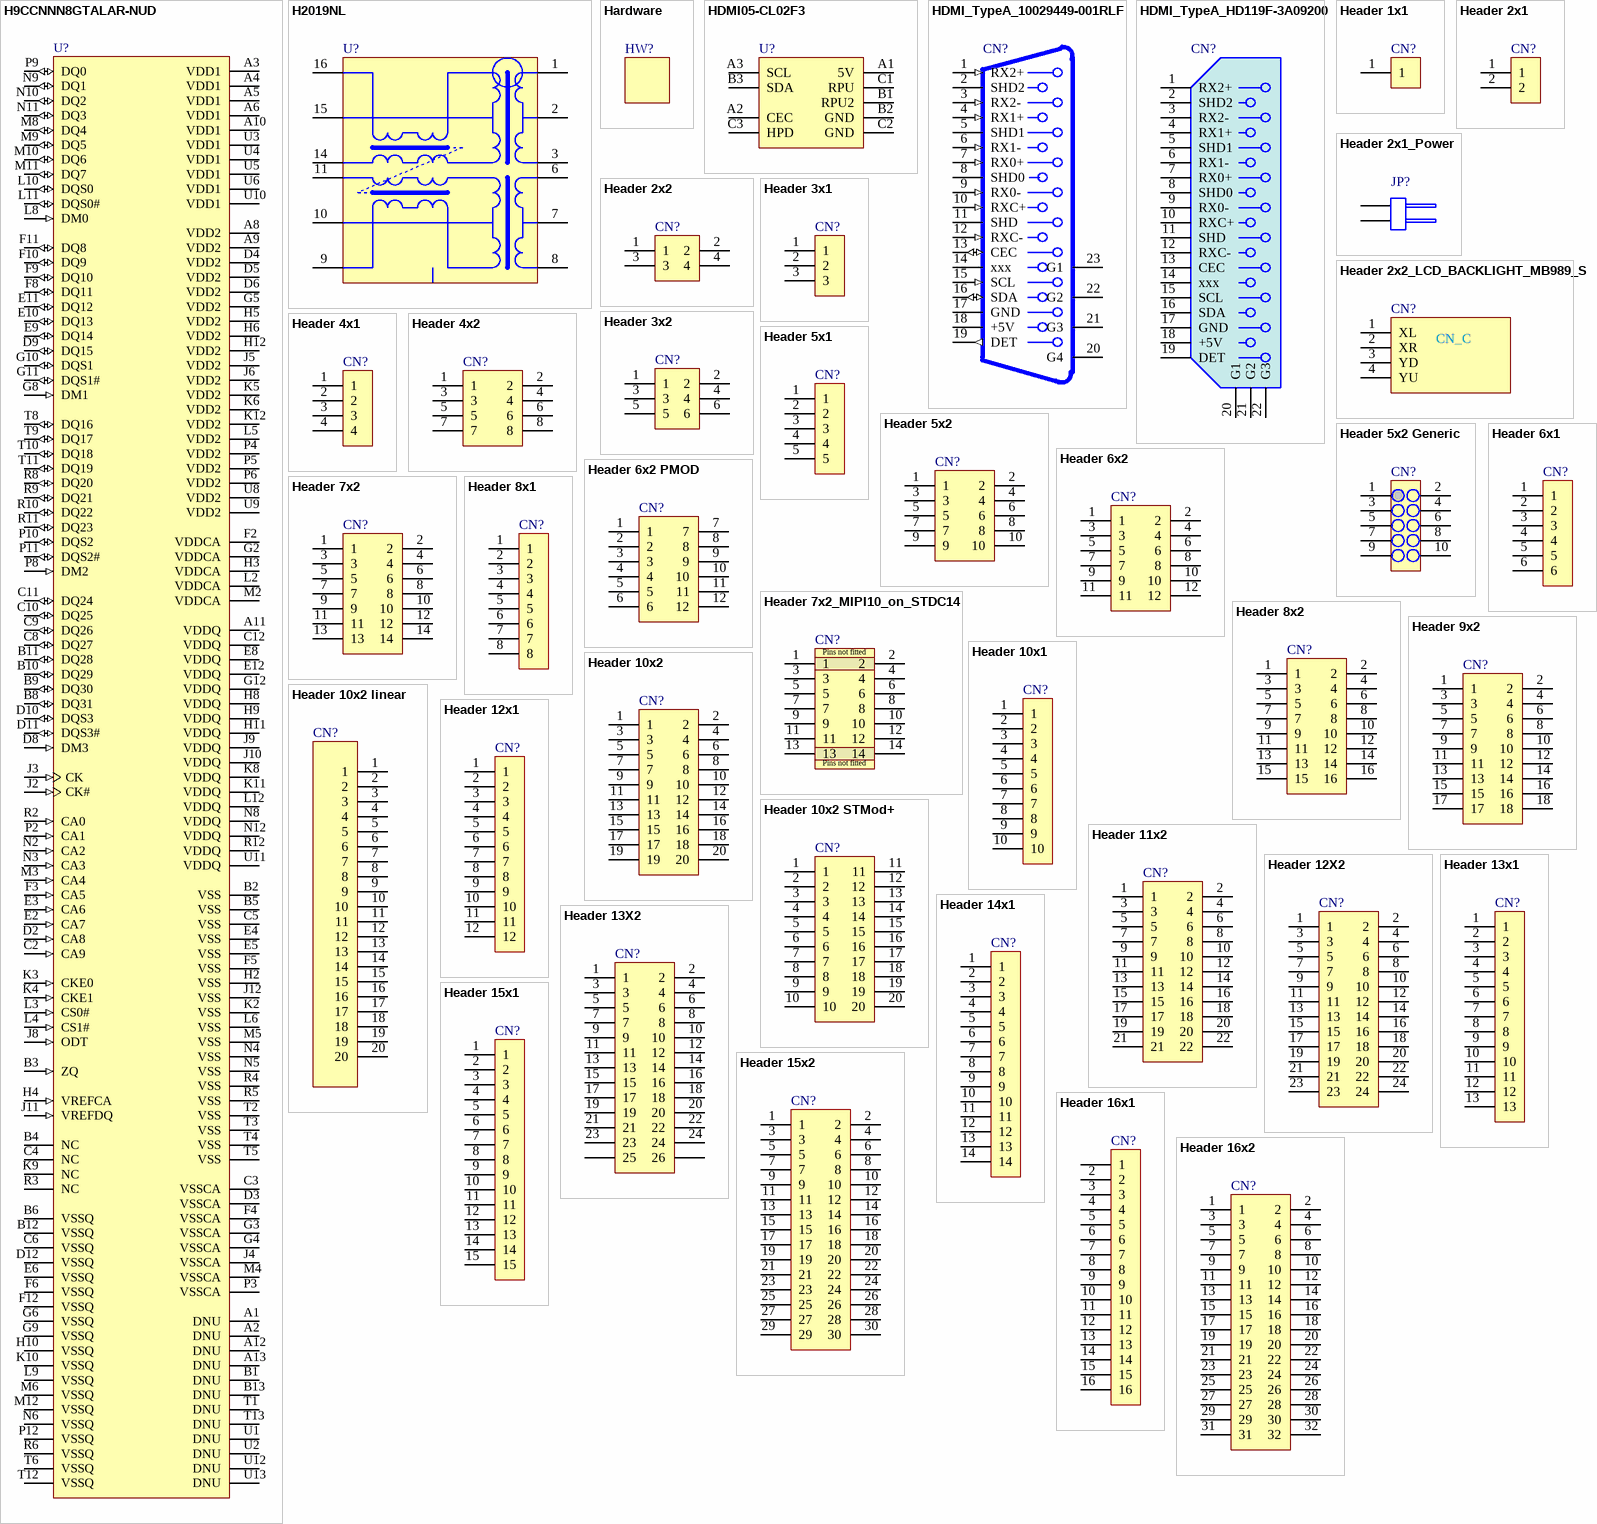
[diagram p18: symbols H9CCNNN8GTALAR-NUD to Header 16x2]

## H9CCNNN8GTALAR-NUD
designator U?
pins: A1 DNU "Do not use: Must be grounded or left floating.", A2 DNU "Do not use: Must be grounded or left floating.", A3 VDD1 (power) "Core power: Supply 1.", A4 VDD1 (power) "Core power: Supply 1.", A5 VDD1 (power) "Core power: Supply 1.", A6 VDD1 (power) "Core power: Supply 1.", A8 VDD2 (power) "Core power: Supply 2.", A9 VDD2 (power) "Core power: Supply 2.", A10 VDD1 (power) "Core power: Supply 1.", A11 VDDQ (power) "DQ power supply: Isolated on the die for improved noise immunity.", A12 DNU "Do not use: Must be grounded or left floating.", A13 DNU "Do not use: Must be grounded or left floating.", B1 DNU "Do not use: Must be grounded or left floating.", B2 VSS (power) "Common ground.", B3 ZQ (in) "External impedance (240 ohm): This signal is used to calibrate the device output impedance.", B4 NC "No connect: Not internally connected.", B5 VSS (power) "Common ground.", B6 VSSQ (power) "DQ ground: Isolated on the die for improved noise immunity.", B8 DQ31 (io) "Data input/output: Bidirectional data bus.", B9 DQ30 (io) "Data input/output: Bidirectional data bus.", B10 DQ29 (io) "Data input/output: Bidirectional data bus.", B11 DQ28 (io) "Data input/output: Bidirectional data bus.", B12 VSSQ (power) "DQ ground: Isolated on the die for improved noise immunity.", B13 DNU "Do not use: Must be grounded or left floating.", C2 CA9 (in) "Command/address inputs: Provide the command and address inputs accordingto the command truth table.", C3 VSSCA (power) "Command/address ground: Isolated on the die for improved noise immunity.", C4 NC "No connect: Not internally connected.", C5 VSS (power) "Common ground", C6 VSSQ (power) "DQ ground: Isolated on the die for improved noise immunity.", C8 DQ27 (io) "Data input/output: Bidirectional data bus.", C9 DQ26 (io) "Data input/output: Bidirectional data bus.", C10 DQ25 (io) "Data input/output: Bidirectional data bus.", C11 DQ24 (io) "Data input/output: Bidirectional data bus.", C12 VDDQ (power) "DQ power supply: Isolated on the die for improved noise immunity.", D2 CA8 (in) "Command/address inputs: Provide the command and address inputs accordingto the command truth table.", D3 VSSCA (power) "Command/address ground: Isolated on the die for improved noise immunity.", D4 VDD2 (power) "Core power: Supply 2.", D5 VDD2 (power) "Core power: Supply 2.", D6 VDD2 (power) "Core power: Supply 2.", D8 DM3 (in) "Input data mask: DM is an input mask signal for write data. Although DM ballsare input-only, the DM loading is designed to match that of DQ and DQS balls.DM[3:0] is DM for each of the four data bytes, respectively.", D9 DQ15 (io) "Data input/output: Bidirectional data bus.", D10 DQS3 (io) "Data strobe: The data strobe is bidirectional (used for read and write data) andcomplementary (DQS and DQS#). It is edge-aligned output with read data andcentered input with write data. DQS[3:0]/DQS[3:0]# is DQS for each of (See Datasheet)", D11 DQS3# (io) "Data strobe: The data strobe is bidirectional (used for read and write data) andcomplementary (DQS and DQS#). It is edge-aligned output with read data andcentered input with write data. DQS[3:0]/DQS[3:0]# is DQS for each of (See Datasheet)", D12 VSSQ (power) "DQ ground: Isolated on the die for improved noise immunity.", E2 CA7 (in) "Command/address inputs: Provide the command and address inputs accordingto the command truth table.", E3 CA6 (in) "Command/address inputs: Provide the command and address inputs accordingto the command truth table.", E4 VSS (power) "Common ground", E5 VSS (power) "Common ground", E6 VSSQ (power) "DQ ground: Isolated on the die for improved noise immunity.", E8 VDDQ (power) "DQ power supply: Isolated on the die for improved noise immunity.", E9 DQ14 (io) "Data input/output: Bidirectional data bus.", E10 DQ13 (io) "Data input/output: Bidirectional data bus.", E11 DQ12 (io) "Data input/output: Bidirectional data bus.", E12 VDDQ (power) "DQ power supply: Isolated on the die for improved noise immunity.", F2 VDDCA (power) "Command/address power supply: Command/address power supply.", F3 CA5 (in) "Command/address inputs: Provide the command and address inputs accordingto the command truth table.", F4 VSSCA (power) "Command/address ground: Isolated on the die for improved noise immunity.", F5 VSS (power) "Common ground", F6 VSSQ (power) "DQ ground: Isolated on the die for improved noise immunity.", F8 DQ11 (io) "Data input/output: Bidirectional data bus.", F9 DQ10 (io) "Data input/output: Bidirectional data bus.", F10 DQ9 (io) "Data input/output: Bidirectional data bus.", F11 DQ8 (io) "Data input/output: Bidirectional data bus.", F12 VSSQ (power) "DQ ground: Isolated on the die for improved noise immunity.", G2 VDDCA (power) "Command/address power supply: Command/address power supply.", G3 VSSCA (power) "Command/address ground: Isolated on the die for improved noise immunity.", G4 VSSCA (power) "Command/address ground: Isolated on the die for improved noise immunity.", G5 VDD2 (power) "Core power: Supply 2.", G6 VSSQ (power) "DQ ground: Isolated on the die for improved noise immunity.", G8 DM1 (in) "Input data mask: DM is an input mask signal for write data. Although DM ballsare input-only, the DM loading is designed to match that of DQ and DQS balls.DM[3:0] is DM for each of the four data bytes, respectively.", G9 VSSQ (power) "DQ ground: Isolated on the die for improved noise immunity.", G10 DQS1 (io) "Data strobe: The data strobe is bidirectional (used for read and write data) andcomplementary (DQS and DQS#). It is edge-aligned output with read data andcentered input with write data. DQS[3:0]/DQS[3:0]# is DQS for each of (See Datasheet)", G11 DQS1# (io) "Data strobe: The data strobe is bidirectional (used for read and write data) andcomplementary (DQS and DQS#). It is edge-aligned output with read data andcentered input with write data. DQS[3:0]/DQS[3:0]# is DQS for each of (See Datasheet)", G12 VDDQ (power) "DQ power supply: Isolated on the die for improved noise immunity.", H2 VSS (power) "Common ground", H3 VDDCA (power) "Command/address power supply: Command/address power supply.", H4 VREFCA (in) "Reference voltage: VREFCA is reference for command/address input buffers,VREFDQ is reference for DQ input buffers.", H5 VDD2 (power) "Core power: Supply 2.", H6 VDD2 (power) "Core power: Supply 2.", H8 VDDQ (power) "DQ power supply: Isolated on the die for improved noise immunity.", H9 VDDQ (power) "DQ power supply: Isolated on the die for improved noise immunity.", H10 VSSQ (power) "DQ ground: Isolated on the die for improved noise immunity.", H11 VDDQ (power) "DQ power supply: Isolated on the die for improved noise immunity.", H12 VDD2 (power) "Core power: Supply 2.", J2 CK# (in) "Clock: CK and CK# are differential clock inputs. All CA inputs are sampled onboth rising and falling edges of CK. CS and CKE inputs are sampled at the risingedge of CK. AC timings are referenced to clock.", J3 CK (in) "Clock: CK and CK# are differential clock inputs. All CA inputs are sampled onboth rising and falling edges of CK. CS and CKE inputs are sampled at the risingedge of CK. AC timings are referenced to clock.", J4 VSSCA (power) "Command/address ground: Isolated on the die for improved noise immunity.", J5 VDD2 (power) "Core power: Supply 2.", J6 VDD2 (power) "Core power: Supply 2.", J8 ODT (in), J9 VDDQ (power) "DQ power supply: Isolated on the die for improved noise immunity.", J10 VDDQ (power) "DQ power supply: Isolated on the die for improved noise immunity.", J11 VREFDQ (in) "Reference voltage: VREFCA is reference for command/address input buffers,VREFDQ is reference for DQ input buffers.", J12 VSS (power) "Common ground", K2 VSS (power) "Common ground", K3 CKE0 (in) "Clock enable: CKE HIGH activates and CKE LOW deactivates the internal clocksignals, input buffers, and output drivers. Power-saving modes are entered andexited via CKE transitions. CKE is considered part of the command code. (See Datasheet)", K4 CKE1 (in) "Clock enable: CKE HIGH activates and CKE LOW deactivates the internal clocksignals, input buffers, and output drivers. Power-saving modes are entered andexited via CKE transitions. CKE is considered part of the command code. (See Datasheet)", K5 VDD2 (power) "Core power: Supply 2.", K6 VDD2 (power) "Core power: Supply 2.", K8 VDDQ (power) "DQ power supply: Isolated on the die for improved noise immunity.", K9 NC "No connect: Not internally connected.", K10 VSSQ (power) "DQ ground: Isolated on the die for improved noise immunity.", K11 VDDQ (power) "DQ power supply: Isolated on the die for improved noise immunity.", K12 VDD2 (power) "Core power: Supply 2.", L2 VDDCA (power) "Command/address power supply: Command/address power supply.", L3 CS0# (in) "Chip select: CS# is considered part of the command code and is sampled at therising edge of CK.", L4 CS1# (in) "Chip select: CS# is considered part of the command code and is sampled at therising edge of CK.", L5 VDD2 (power) "Core power: Supply 2.", L6 VSS (power) "Common ground", L8 DM0 (in) "Input data mask: DM is an input mask signal for write data. Although DM ballsare input-only, the DM loading is designed to match that of DQ and DQS balls.DM[3:0] is DM for each of the four data bytes, respectively.", L9 VSSQ (power) "DQ ground: Isolated on the die for improved noise immunity.", L10 DQS0 (io) "Data strobe: The data strobe is bidirectional (used for read and write data) andcomplementary (DQS and DQS#). It is edge-aligned output with read data andcentered input with write data. DQS[3:0]/DQS[3:0]# is DQS for each of (See Datasheet)", L11 DQS0# (io) "Data strobe: The data strobe is bidirectional (used for read and write data) andcomplementary (DQS and DQS#). It is edge-aligned output with read data andcentered input with write data. DQS[3:0]/DQS[3:0]# is DQS for each of (See Datasheet)", L12 VDDQ (power) "DQ power supply: Isolated on the die for improved noise immunity.", M2 VDDCA (power) "Command/address power supply: Command/address power supply.", M3 CA4 (in) "Command/address inputs: Provide the command and address inputs accordingto the command truth table.", M4 VSSCA (power) "Command/address ground: Isolated on the die for improved noise immunity.", M5 VSS (power) "Common ground", M6 VSSQ (power) "DQ ground: Isolated on the die for improved noise immunity.", M8 DQ4 (io) "Data input/output: Bidirectional data bus.", M9 DQ5 (io) "Data input/output: Bidirectional data bus.", M10 DQ6 (io) "Data input/output: Bidirectional data bus.", M11 DQ7 (io) "Data input/output: Bidirectional data bus.", M12 VSSQ (power) "DQ ground: Isolated on the die for improved noise immunity.", N2 CA2 (in) "Command/address inputs: Provide the command and address inputs accordingto the command truth table.", N3 CA3 (in) "Command/address inputs: Provide the command and address inputs accordingto the command truth table.", N4 VSS (power) "Common ground", N5 VSS (power) "Common ground", N6 VSSQ (power) "DQ ground: Isolated on the die for improved noise immunity.", N8 VDDQ (power) "DQ power supply: Isolated on the die for improved noise immunity.", N9 DQ1 (io) "Data input/output: Bidirectional data bus.", N10 DQ2 (io) "Data input/output: Bidirectional data bus.", N11 DQ3 (io) "Data input/output: Bidirectional data bus.", N12 VDDQ (power) "DQ power supply: Isolated on the die for improved noise immunity.", P2 CA1 (in) "Command/address inputs: Provide the command and address inputs accordingto the command truth table.", P3 VSSCA (power) "Command/address ground: Isolated on the die for improved noise immunity.", P4 VDD2 (power) "Core power: Supply 2.", P5 VDD2 (power) "Core power: Supply 2.", P6 VDD2 (power) "Core power: Supply 2.", P8 DM2 (in) "Input data mask: DM is an input mask signal for write data. Although DM ballsare input-only, the DM loading is designed to match that of DQ and DQS balls.DM[3:0] is DM for each of the four data bytes, respectively.", P9 DQ0 (io) "Data input/output: Bidirectional data bus.", P10 DQS2 (io) "Data strobe: The data strobe is bidirectional (used for read and write data) andcomplementary (DQS and DQS#). It is edge-aligned output with read data andcentered input with write data. DQS[3:0]/DQS[3:0]# is DQS for each of (See Datasheet)", P11 DQS2# (io) "Data strobe: The data strobe is bidirectional (used for read and write data) andcomplementary (DQS and DQS#). It is edge-aligned output with read data andcentered input with write data. DQS[3:0]/DQS[3:0]# is DQS for each of (See Datasheet)", P12 VSSQ (power) "DQ ground: Isolated on the die for improved noise immunity.", R2 CA0 (in) "Command/address inputs: Provide the command and address inputs accordingto the command truth table.", R3 NC "No connect: Not internally connected.", R4 VSS (power) "Common ground", R5 VSS (power) "Common ground", R6 VSSQ (power) "DQ power supply: Isolated on the die for improved noise immunity.", R8 DQ20 (io) "Data input/output: Bidirectional data bus.", R9 DQ21 (io) "Data input/output: Bidirectional data bus.", R10 DQ22 (io) "Data input/output: Bidirectional data bus.", R11 DQ23 (io) "Data input/output: Bidirectional data bus.", R12 VDDQ (power) "DQ power supply: Isolated on the die for improved noise immunity.", T1 DNU "Do not use: Must be grounded or left floating.", T2 VSS (power) "Common ground", T3 VSS (power) "Common ground", T4 VSS (power) "Common ground", T5 VSS (power) "Common ground", T6 VSSQ (power) "DQ power supply: Isolated on the die for improved noise immunity.", T8 DQ16 (io) "Data input/output: Bidirectional data bus.", T9 DQ17 (io) "Data input/output: Bidirectional data bus.", T10 DQ18 (io) "Data input/output: Bidirectional data bus.", T11 DQ19 (io) "Data input/output: Bidirectional data bus.", T12 VSSQ (power) "DQ power supply: Isolated on the die for improved noise immunity.", T13 DNU "Do not use: Must be grounded or left floating.", U1 DNU "Do not use: Must be grounded or left floating.", U2 DNU "Do not use: Must be grounded or left floating.", U3 VDD1 (power) "Core power: Supply 1.", U4 VDD1 (power) "Core power: Supply 1.", U5 VDD1 (power) "Core power: Supply 1.", U6 VDD1 (power) "Core power: Supply 1.", U8 VDD2 (power) "Core power: Supply 2.", U9 VDD2 (power) "Core power: Supply 2.", U10 VDD1 (power) "Core power: Supply 1.", U11 VDDQ (power) "Core power: Supply 2.", U12 DNU "Do not use: Must be grounded or left floating.", U13 DNU "Do not use: Must be grounded or left floating."

## H2019NL
designator U?
pins: 1 td+, 2 tct, 3 td-, 6 rd+, 7 rct, 8 rd-, 9 rx-, 10 rxct, 11 rx1+, 14 tx1-, 15 txct, 16 tx1+

## Hardware
designator HW?  (mechanical)

## HDMI05-CL02F3
designator U?
pins: A1 5V, A2 CEC, A3 SCL, B1 RPU2, B2 GND, B3 SDA, C1 RPU, C2 GND, C3 HPD

## HDMI_TypeA_10029449-001RLF
designator CN?
pins: 1 RX2+ (in), 2 SHD2, 3 RX2- (in), 4 RX1+ (in), 5 SHD1, 6 RX1- (in), 7 RX0+ (in), 8 SHD0, 9 RX0- (in), 10 RXC+ (in), 11 SHD, 12 RXC- (in), 13 CEC (io), 14 xxx, 15 SCL (in), 16 SDA (io), 17 GND, 18 +5V (power), 19 DET (out), 20 G4, 21 G3, 22 G2, 23 G1

## HDMI_TypeA_HD119F-3A09200
designator CN?
pins: 1 RX2+, 2 SHD2, 3 RX2-, 4 RX1+, 5 SHD1, 6 RX1-, 7 RX0+, 8 SHD0, 9 RX0-, 10 RXC+, 11 SHD, 12 RXC-, 13 CEC, 14 xxx, 15 SCL, 16 SDA, 17 GND, 18 +5V, 19 DET, 20 G1, 21 G2, 22 G3

## Header 1x1
designator CN?
pins: 1

## Header 2x1
designator CN?
pins: 1, 2

## Header 2x1_Power
designator JP?
pins: 1 COMMON, 2 NO

## Header 2x2
designator CN?
pins: 1, 2, 3, 4

## Header 2x2_LCD_BACKLIGHT_MB989_S
designator CN?
pins: 1 XL, 2 XR, 3 YD, 4 YU

## Header 3x1
designator CN?
pins: 1, 2, 3
1 alternate drawing of the same symbol

## Header 3x2
designator CN?
pins: 1, 2, 3, 4, 5, 6

## Header 4x1
designator CN?
pins: 1, 2, 3, 4

## Header 4x2
designator CN?
pins: 1, 2, 3, 4, 5, 6, 7, 8

## Header 5x1
designator CN?
pins: 1, 2, 3, 4, 5

## Header 5x2
designator CN?
pins: 1, 2, 3, 4, 5, 6, 7, 8, 9, 10

## Header 5x2 Generic
designator CN?
pins: 1, 2, 3, 4, 5, 6, 7, 8, 9, 10

## Header 6x1
designator CN?
pins: 1, 2, 3, 4, 5, 6

## Header 6x2
designator CN?
pins: 1, 2, 3, 4, 5, 6, 7, 8, 9, 10, 11, 12

## Header 6x2 PMOD
designator CN?
pins: 1, 2, 3, 4, 5, 6, 7, 8, 9, 10, 11, 12

## Header 7x2
designator CN?
pins: 1, 2, 3, 4, 5, 6, 7, 8, 9, 10, 11, 12, 13, 14

## Header 7x2_MIPI10_on_STDC14
designator CN?
pins: 1, 2, 3, 4, 5, 6, 7, 8, 9, 10, 11, 12, 13, 14

## Header 8x1
designator CN?
pins: 1, 2, 3, 4, 5, 6, 7, 8

## Header 8x2
designator CN?
pins: 1, 2, 3, 4, 5, 6, 7, 8, 9, 10, 11, 12, 13, 14, 15, 16

## Header 9x2
designator CN?
pins: 1, 2, 3, 4, 5, 6, 7, 8, 9, 10, 11, 12, 13, 14, 15, 16, 17, 18

## Header 10x1
designator CN?
pins: 1, 2, 3, 4, 5, 6, 7, 8, 9, 10

## Header 10x2
designator CN?
pins: 1, 2, 3, 4, 5, 6, 7, 8, 9, 10, 11, 12, 13, 14, 15, 16, 17, 18, 19, 20
1 alternate drawing of the same symbol

## Header 10x2 linear
designator CN?
An alternate mode is available
pins: 1, 2, 3, 4, 5, 6, 7, 8, 9, 10, 11, 12, 13, 14, 15, 16, 17, 18, 19, 20
1 alternate drawing of the same symbol

## Header 10x2 STMod+
designator CN?
pins: 1, 2, 3, 4, 5, 6, 7, 8, 9, 10, 11, 12, 13, 14, 15, 16, 17, 18, 19, 20

## Header 11x2
designator CN?
pins: 1, 2, 3, 4, 5, 6, 7, 8, 9, 10, 11, 12, 13, 14, 15, 16, 17, 18, 19, 20, 21, 22

## Header 12x1
designator CN?
pins: 1, 2, 3, 4, 5, 6, 7, 8, 9, 10, 11, 12

## Header 12X2
designator CN?
pins: 1, 2, 3, 4, 5, 6, 7, 8, 9, 10, 11, 12, 13, 14, 15, 16, 17, 18, 19, 20, 21, 22, 23, 24

## Header 13x1
designator CN?
pins: 1, 2, 3, 4, 5, 6, 7, 8, 9, 10, 11, 12, 13

## Header 13X2
designator CN?
pins: 1, 2, 3, 4, 5, 6, 7, 8, 9, 10, 11, 12, 13, 14, 15, 16, 17, 18, 19, 20, 21, 22, 23, 24, 25, 26

## Header 14x1
designator CN?
pins: 1, 2, 3, 4, 5, 6, 7, 8, 9, 10, 11, 12, 13, 14

## Header 15x1
designator CN?
pins: 1, 2, 3, 4, 5, 6, 7, 8, 9, 10, 11, 12, 13, 14, 15

## Header 15x2
designator CN?
pins: 1, 2, 3, 4, 5, 6, 7, 8, 9, 10, 11, 12, 13, 14, 15, 16, 17, 18, 19, 20, 21, 22, 23, 24, 25, 26, 27, 28, 29, 30

## Header 16x1
designator CN?
pins: 1, 2, 3, 4, 5, 6, 7, 8, 9, 10, 11, 12, 13, 14, 15, 16

## Header 16x2
designator CN?
pins: 1, 2, 3, 4, 5, 6, 7, 8, 9, 10, 11, 12, 13, 14, 15, 16, 17, 18, 19, 20, 21, 22, 23, 24, 25, 26, 27, 28, 29, 30, 31, 32
1 alternate drawing of the same symbol

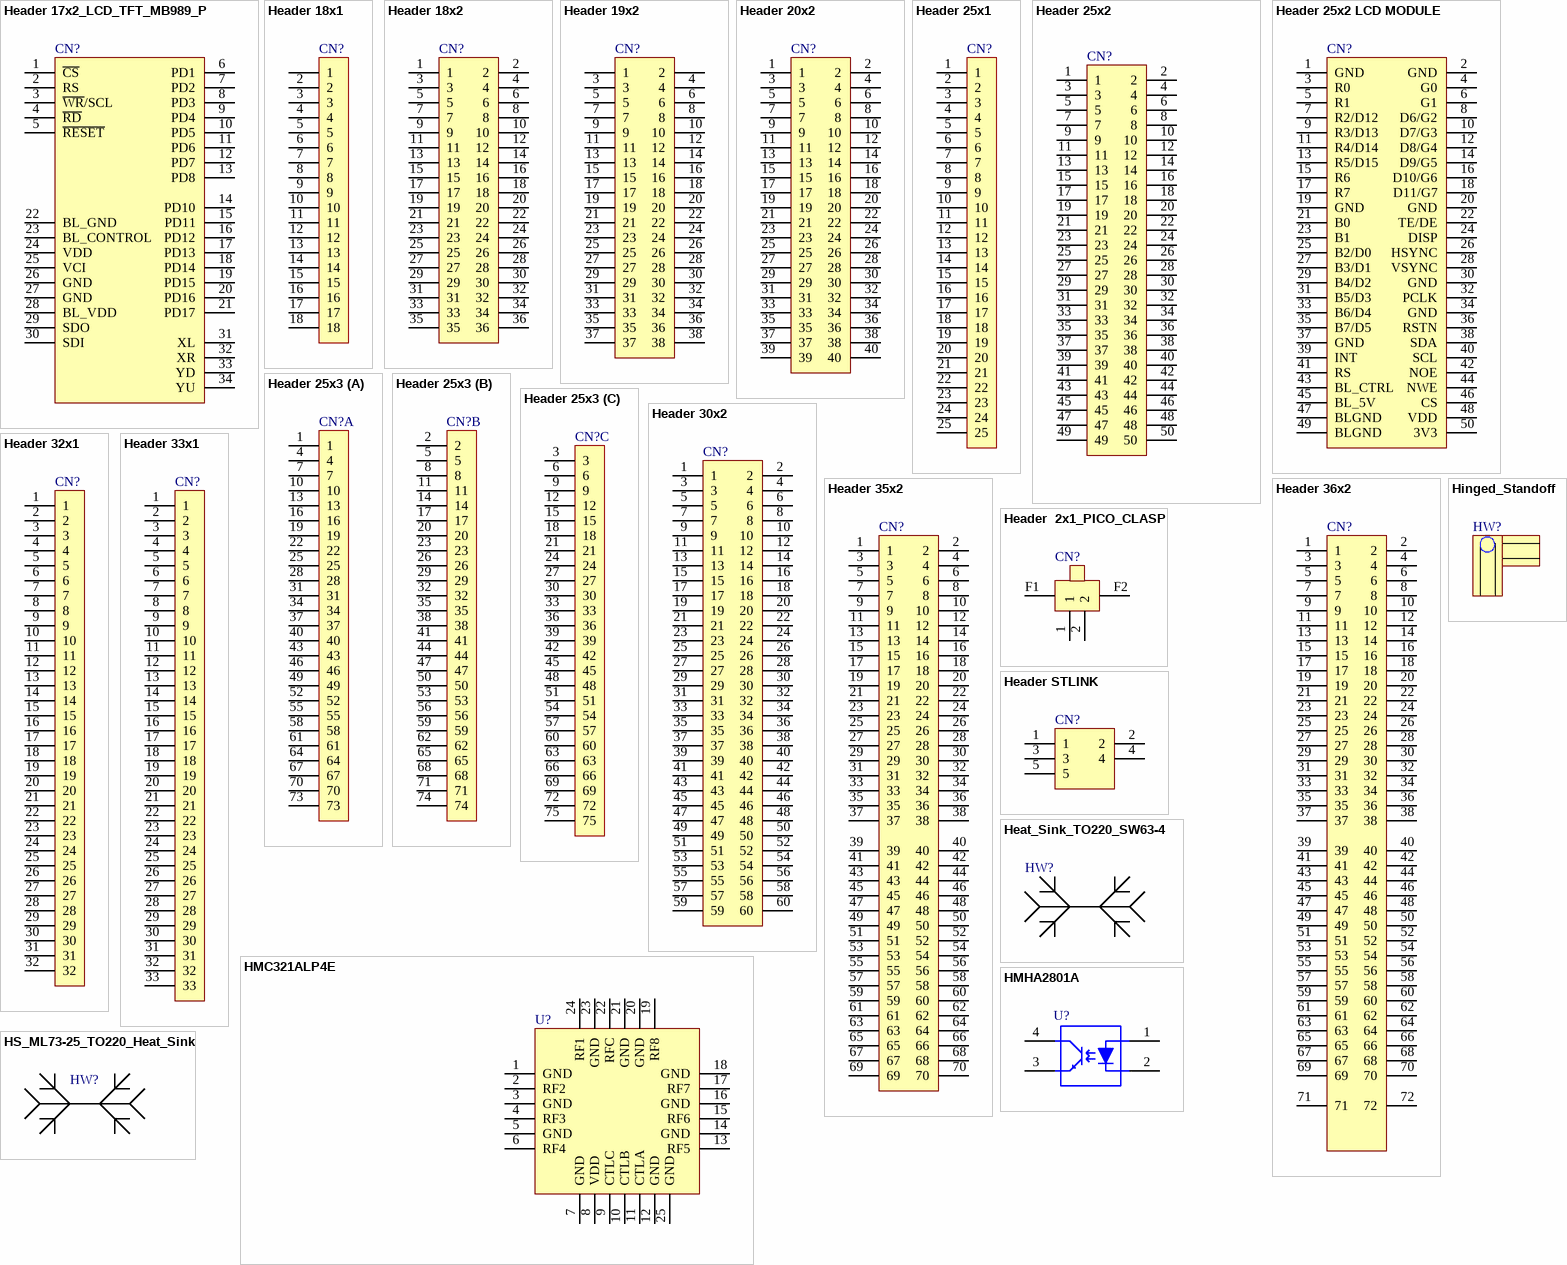
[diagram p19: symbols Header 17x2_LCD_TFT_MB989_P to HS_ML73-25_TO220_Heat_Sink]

## Header 17x2_LCD_TFT_MB989_P
designator CN?
pins: 1 ~{CS}, 2 RS, 3 ~{WR}/SCL, 4 ~{RD}, 5 ~{RESET}, 6 PD1, 7 PD2, 8 PD3, 9 PD4, 10 PD5, 11 PD6, 12 PD7, 13 PD8, 14 PD10, 15 PD11, 16 PD12, 17 PD13, 18 PD14, 19 PD15, 20 PD16, 21 PD17, 22 BL_GND, 23 BL_CONTROL, 24 VDD, 25 VCI, 26 GND, 27 GND, 28 BL_VDD, 29 SDO, 30 SDI, 31 XL, 32 XR, 33 YD, 34 YU

## Header 18x1
designator CN?
pins: 1, 2, 3, 4, 5, 6, 7, 8, 9, 10, 11, 12, 13, 14, 15, 16, 17, 18

## Header 18x2
designator CN?
pins: 1, 2, 3, 4, 5, 6, 7, 8, 9, 10, 11, 12, 13, 14, 15, 16, 17, 18, 19, 20, 21, 22, 23, 24, 25, 26, 27, 28, 29, 30, 31, 32, 33, 34, 35, 36

## Header 19x2
designator CN?
An alternate mode is available
pins: 1, 2, 3, 4, 5, 6, 7, 8, 9, 10, 11, 12, 13, 14, 15, 16, 17, 18, 19, 20, 21, 22, 23, 24, 25, 26, 27, 28, 29, 30, 31, 32, 33, 34, 35, 36, 37, 38
2 alternate drawings of the same symbol

## Header 20x2
designator CN?
pins: 1, 2, 3, 4, 5, 6, 7, 8, 9, 10, 11, 12, 13, 14, 15, 16, 17, 18, 19, 20, 21, 22, 23, 24, 25, 26, 27, 28, 29, 30, 31, 32, 33, 34, 35, 36, 37, 38, 39, 40

## Header 25x1
designator CN?
pins: 1, 2, 3, 4, 5, 6, 7, 8, 9, 10, 11, 12, 13, 14, 15, 16, 17, 18, 19, 20, 21, 22, 23, 24, 25

## Header 25x2
designator CN?
pins: 1, 2, 3, 4, 5, 6, 7, 8, 9, 10, 11, 12, 13, 14, 15, 16, 17, 18, 19, 20, 21, 22, 23, 24, 25, 26, 27, 28, 29, 30, 31, 32, 33, 34, 35, 36, 37, 38, 39, 40, 41, 42, 43, 44, 45, 46, 47, 48, 49, 50

## Header 25x2 LCD MODULE
designator CN?
pins: 1 GND, 2 GND, 3 R0, 4 G0, 5 R1, 6 G1, 7 R2/D12, 8 D6/G2, 9 R3/D13, 10 D7/G3, 11 R4/D14, 12 D8/G4, 13 R5/D15, 14 D9/G5, 15 R6, 16 D10/G6, 17 R7, 18 D11/G7, 19 GND, 20 GND, 21 B0, 22 TE/DE, 23 B1, 24 DISP, 25 B2/D0, 26 HSYNC, 27 B3/D1, 28 VSYNC, 29 B4/D2, 30 GND, 31 B5/D3, 32 PCLK, 33 B6/D4, 34 GND, 35 B7/D5, 36 RSTN, 37 GND, 38 SDA, 39 INT, 40 SCL, 41 RS, 42 NOE, 43 BL_CTRL, 44 NWE, 45 BL_5V, 46 CS, 47 BLGND, 48 VDD, 49 BLGND, 50 3V3
2 alternate drawings of the same symbol

## Header 25x3
designator CN?
part A pins: 1, 4, 7, 10, 13, 16, 19, 22, 25, 28, 31, 34, 37, 40, 43, 46, 49, 52, 55, 58, 61, 64, 67, 70, 73
part B pins: 2, 5, 8, 11, 14, 17, 20, 23, 26, 29, 32, 35, 38, 41, 44, 47, 50, 53, 56, 59, 62, 65, 68, 71, 74
part C pins: 3, 6, 9, 12, 15, 18, 21, 24, 27, 30, 33, 36, 39, 42, 45, 48, 51, 54, 57, 60, 63, 66, 69, 72, 75

## Header 30x2
designator CN?
pins: 1, 2, 3, 4, 5, 6, 7, 8, 9, 10, 11, 12, 13, 14, 15, 16, 17, 18, 19, 20, 21, 22, 23, 24, 25, 26, 27, 28, 29, 30, 31, 32, 33, 34, 35, 36, 37, 38, 39, 40, 41, 42, 43, 44, 45, 46, 47, 48, 49, 50, 51, 52, 53, 54, 55, 56, 57, 58, 59, 60

## Header 32x1
designator CN?
pins: 1, 2, 3, 4, 5, 6, 7, 8, 9, 10, 11, 12, 13, 14, 15, 16, 17, 18, 19, 20, 21, 22, 23, 24, 25, 26, 27, 28, 29, 30, 31, 32

## Header 33x1
designator CN?
pins: 1, 2, 3, 4, 5, 6, 7, 8, 9, 10, 11, 12, 13, 14, 15, 16, 17, 18, 19, 20, 21, 22, 23, 24, 25, 26, 27, 28, 29, 30, 31, 32, 33

## Header 35x2
designator CN?
pins: 1, 2, 3, 4, 5, 6, 7, 8, 9, 10, 11, 12, 13, 14, 15, 16, 17, 18, 19, 20, 21, 22, 23, 24, 25, 26, 27, 28, 29, 30, 31, 32, 33, 34, 35, 36, 37, 38, 39, 40, 41, 42, 43, 44, 45, 46, 47, 48, 49, 50, 51, 52, 53, 54, 55, 56, 57, 58, 59, 60, 61, 62, 63, 64, 65, 66, 67, 68, 69, 70

## Header 36x2
designator CN?
pins: 1, 2, 3, 4, 5, 6, 7, 8, 9, 10, 11, 12, 13, 14, 15, 16, 17, 18, 19, 20, 21, 22, 23, 24, 25, 26, 27, 28, 29, 30, 31, 32, 33, 34, 35, 36, 37, 38, 39, 40, 41, 42, 43, 44, 45, 46, 47, 48, 49, 50, 51, 52, 53, 54, 55, 56, 57, 58, 59, 60, 61, 62, 63, 64, 65, 66, 67, 68, 69, 70, 71, 72

## Header  2x1_PICO_CLASP
designator CN?
pins: 1, 2, F1 F2, F2

## Header STLINK
designator CN?
pins: 1, 2, 3, 4, 5

## Heat_Sink_TO220_SW63-4
designator HW?

## Hinged_Standoff
designator HW?  (mechanical)

## HMC321ALP4E
designator U?
pins: 1 GND, 2 RF2, 3 GND, 4 RF3, 5 GND, 6 RF4, 7 GND, 8 VDD, 9 CTLC, 10 CTLB, 11 CTLA, 12 GND, 13 RF5, 14 GND, 15 RF6, 16 GND, 17 RF7, 18 GND, 19 RF8, 20 GND, 21 GND, 22 RFC, 23 GND, 24 RF1, 25 GND

## HMHA2801A
designator U?
pins: 1 Anode, 2 B, 3 Emitter, 4 Collector

## HS_ML73-25_TO220_Heat_Sink
designator HW?

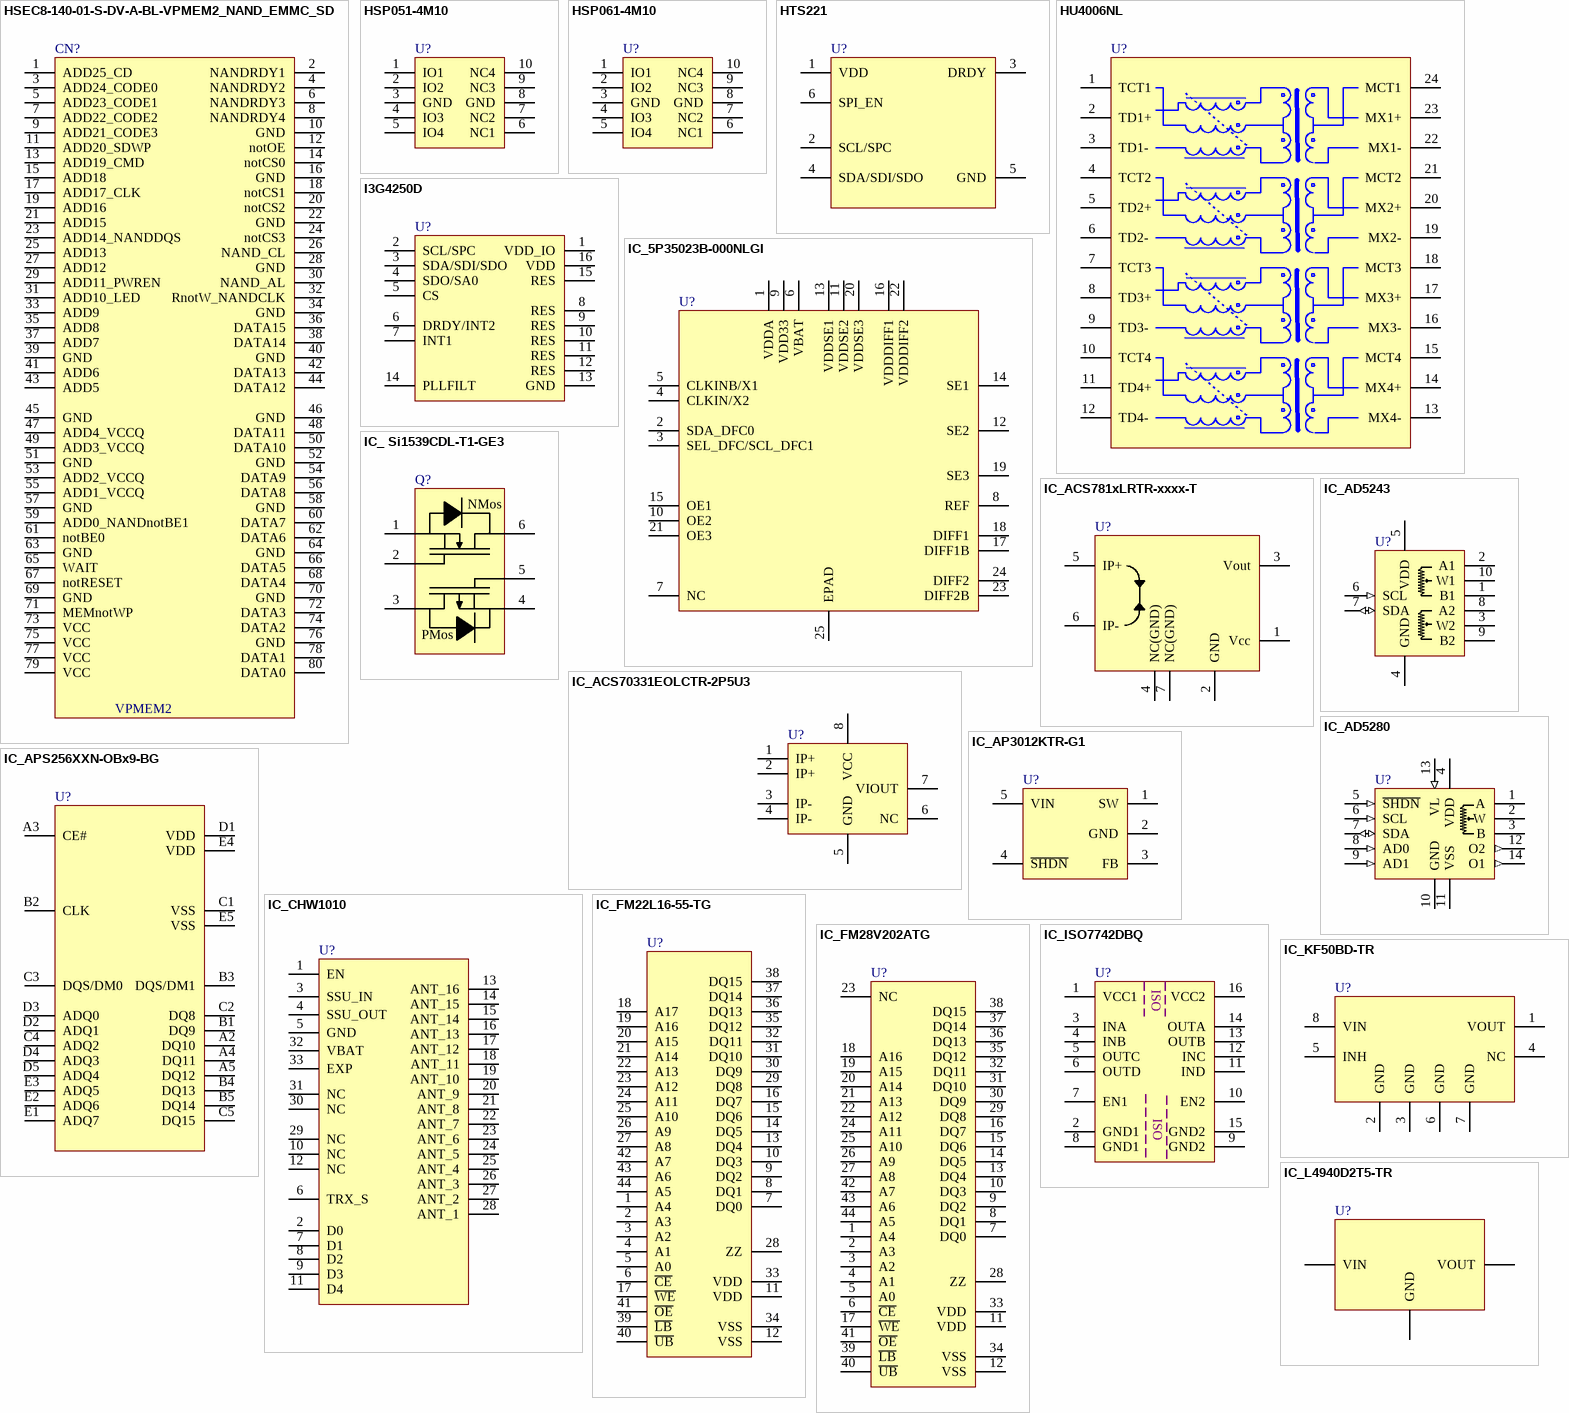
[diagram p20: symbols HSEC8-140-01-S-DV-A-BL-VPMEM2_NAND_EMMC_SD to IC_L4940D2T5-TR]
